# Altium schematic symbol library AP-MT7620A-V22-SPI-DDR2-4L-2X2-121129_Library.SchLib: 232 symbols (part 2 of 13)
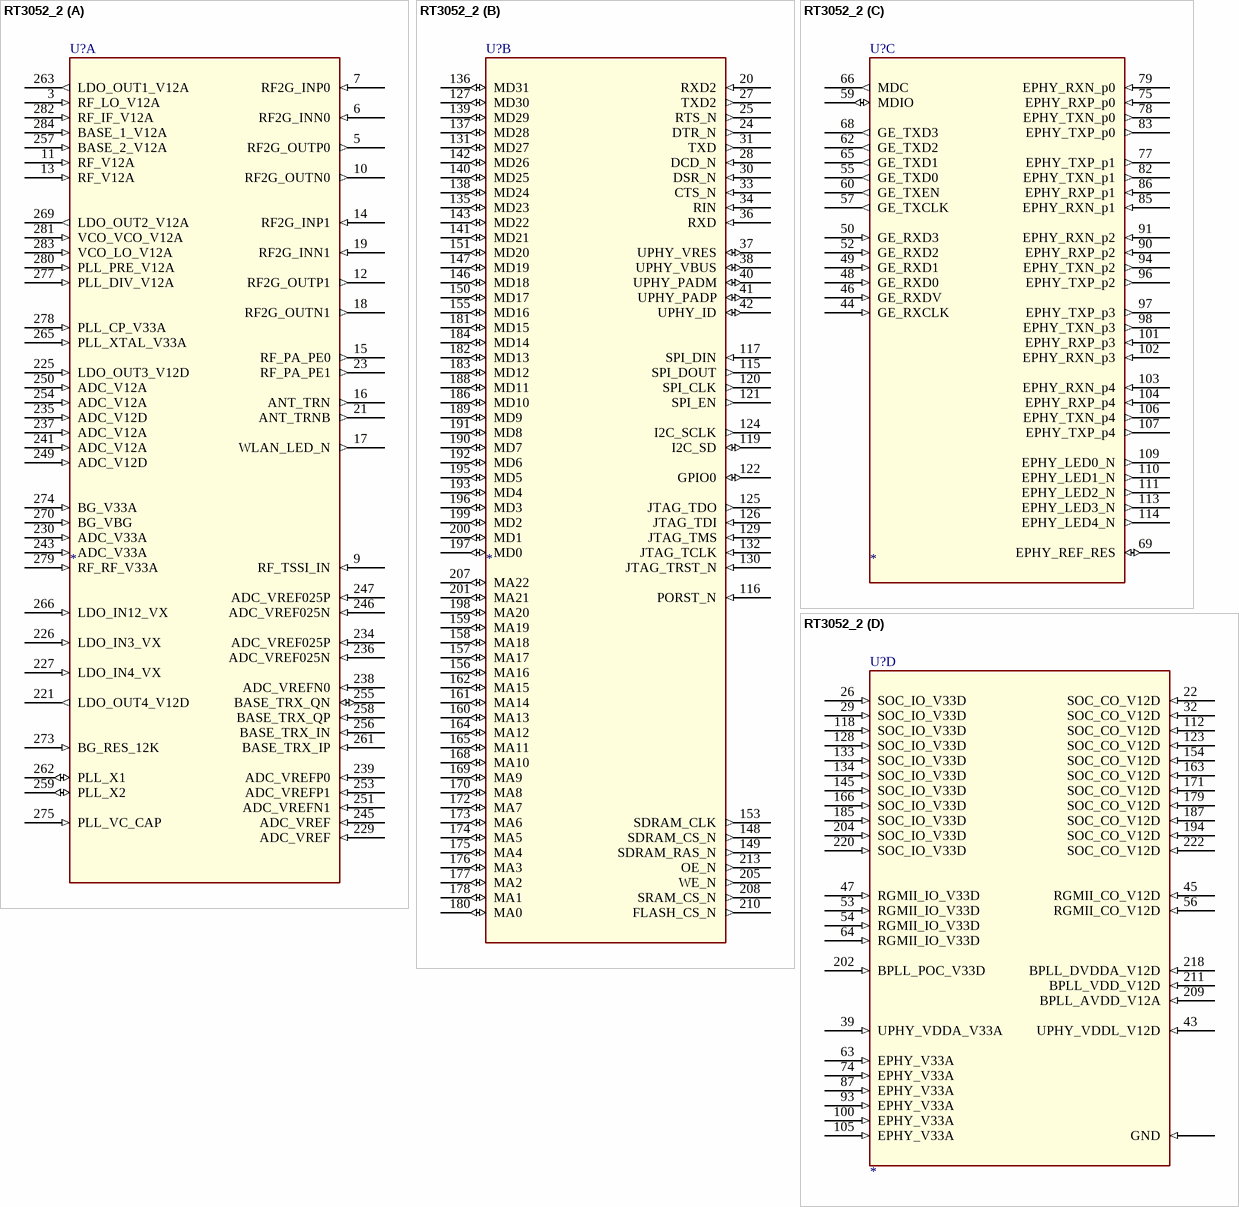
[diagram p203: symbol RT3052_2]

## RT3052_2
designator U?
footprint QFN285
part A pins: 3 RF_LO_V12A (in), 5 RF2G_OUTP0 (out), 6 RF2G_INN0 (in), 7 RF2G_INP0 (in), 9 RF_TSSI_IN (in), 10 RF2G_OUTN0 (out), 11 RF_V12A (in), 12 RF2G_OUTP1 (out), 13 RF_V12A (in), 14 RF2G_INP1 (in), 15 RF_PA_PE0 (out), 16 ANT_TRN (out), 17 WLAN_LED_N (out), 18 RF2G_OUTN1 (out), 19 RF2G_INN1 (in), 21 ANT_TRNB (out), 23 RF_PA_PE1 (out), 221 LDO_OUT4_V12D (out), 225 LDO_OUT3_V12D (in), 226 LDO_IN3_VX (in), 227 LDO_IN4_VX (in), 229 ADC_VREF (in), 230 ADC_V33A (in), 234 ADC_VREF025P (in), 235 ADC_V12D (in), 236 ADC_VREF025N (in), 237 ADC_V12A (in), 238 ADC_VREFN0 (in), 239 ADC_VREFP0 (in), 241 ADC_V12A (in), 243 ADC_V33A (in), 245 ADC_VREF (in), 246 ADC_VREF025N (in), 247 ADC_VREF025P (in), 249 ADC_V12D (in), 250 ADC_V12A (in), 251 ADC_VREFN1 (in), 253 ADC_VREFP1 (in), 254 ADC_V12A (in), 255 BASE_TRX_QN (io), 256 BASE_TRX_IN (in), 257 BASE_2_V12A (in), 258 BASE_TRX_QP (in), 259 PLL_X2 (io), 261 BASE_TRX_IP (in), 262 PLL_X1 (io), 263 LDO_OUT1_V12A (out), 265 PLL_XTAL_V33A (in), 266 LDO_IN12_VX (in), 269 LDO_OUT2_V12A (out), 270 BG_VBG (in), 273 BG_RES_12K (in), 274 BG_V33A (in), 275 PLL_VC_CAP (in), 277 PLL_DIV_V12A (in), 278 PLL_CP_V33A (in), 279 RF_RF_V33A (in), 280 PLL_PRE_V12A (in), 281 VCO_VCO_V12A (in), 282 RF_IF_V12A (in), 283 VCO_LO_V12A (in), 284 BASE_1_V12A (in)
part B pins: 20 RXD2 (in), 24 DTR_N (out), 25 RTS_N (out), 27 TXD2 (out), 28 DCD_N (in), 30 DSR_N (in), 31 TXD (out), 33 CTS_N (in), 34 RIN (in), 36 RXD (in), 37 UPHY_VRES (io), 38 UPHY_VBUS (io), 40 UPHY_PADM (io), 41 UPHY_PADP (io), 42 UPHY_ID (io), 115 SPI_DOUT (out), 116 PORST_N (in), 117 SPI_DIN (in), 119 I2C_SD (io), 120 SPI_CLK (out), 121 SPI_EN (out), 122 GPIO0 (io), 124 I2C_SCLK (out), 125 JTAG_TDO (out), 126 JTAG_TDI (in), 127 MD30 (io), 129 JTAG_TMS (in), 130 JTAG_TRST_N (in), 131 MD27 (io), 132 JTAG_TCLK (in), 135 MD23 (io), 136 MD31 (io), 137 MD28 (io), 138 MD24 (io), 139 MD29 (io), 140 MD25 (io), 141 MD21 (io), 142 MD26 (io), 143 MD22 (io), 146 MD18 (io), 147 MD19 (io), 148 SDRAM_CS_N (out), 149 SDRAM_RAS_N (out), 150 MD17 (io), 151 MD20 (io), 153 SDRAM_CLK (out), 155 MD16 (io), 156 MA16 (io), 157 MA17 (io), 158 MA18 (io), 159 MA19 (io), 160 MA13 (io), 161 MA14 (io), 162 MA15 (io), 164 MA12 (io), 165 MA11 (io), 168 MA10 (io), 169 MA9 (io), 170 MA8 (io), 172 MA7 (io), 173 MA6 (io), 174 MA5 (io), 175 MA4 (io), 176 MA3 (io), 177 MA2 (io), 178 MA1 (io), 180 MA0 (io), 181 MD15 (io), 182 MD13 (io), 183 MD12 (io), 184 MD14 (io), 186 MD10 (io), 188 MD11 (io), 189 MD9 (io), 190 MD7 (io), 191 MD8 (io), 192 MD6 (io), 193 MD4 (io), 195 MD5 (io), 196 MD3 (io), 197 MD0 (io), 198 MA20 (io), 199 MD2 (io), 200 MD1 (io), 201 MA21 (io), 205 WE_N (out), 207 MA22 (io), 208 SRAM_CS_N (out), 210 FLASH_CS_N (out), 213 OE_N (out)
part C pins: 44 GE_RXCLK (in), 46 GE_RXDV (in), 48 GE_RXD0 (in), 49 GE_RXD1 (in), 50 GE_RXD3 (in), 52 GE_RXD2 (in), 55 GE_TXD0 (out), 57 GE_TXCLK (out), 59 MDIO (io), 60 GE_TXEN (out), 62 GE_TXD2 (out), 65 GE_TXD1 (out), 66 MDC (out), 68 GE_TXD3 (out), 69 EPHY_REF_RES (io), 75 EPHY_RXP_p0 (in), 77 EPHY_TXP_p1 (out), 78 EPHY_TXN_p0 (out), 79 EPHY_RXN_p0 (in), 82 EPHY_TXN_p1 (out), 83 EPHY_TXP_p0 (out), 85 EPHY_RXN_p1 (in), 86 EPHY_RXP_p1 (in), 90 EPHY_RXP_p2 (in), 91 EPHY_RXN_p2 (in), 94 EPHY_TXN_p2 (out), 96 EPHY_TXP_p2 (out), 97 EPHY_TXP_p3 (out), 98 EPHY_TXN_p3 (out), 101 EPHY_RXP_p3 (in), 102 EPHY_RXN_p3 (in), 103 EPHY_RXN_p4 (in), 104 EPHY_RXP_p4 (in), 106 EPHY_TXN_p4 (out), 107 EPHY_TXP_p4 (out), 109 EPHY_LED0_N (out), 110 EPHY_LED1_N (out), 111 EPHY_LED2_N (out), 113 EPHY_LED3_N (out), 114 EPHY_LED4_N (out)
part D pins: 22 SOC_CO_V12D (in), 26 SOC_IO_V33D (in), 29 SOC_IO_V33D (in), 32 SOC_CO_V12D (in), 39 UPHY_VDDA_V33A (in), 43 UPHY_VDDL_V12D (in), 45 RGMII_CO_V12D (in), 47 RGMII_IO_V33D (in), 53 RGMII_IO_V33D (in), 54 RGMII_IO_V33D (in), 56 RGMII_CO_V12D (in), 63 EPHY_V33A (in), 64 RGMII_IO_V33D (in), 74 EPHY_V33A (in), 87 EPHY_V33A (in), 93 EPHY_V33A (in), 100 EPHY_V33A (in), 105 EPHY_V33A (in), 112 SOC_CO_V12D (in), 118 SOC_IO_V33D (in), 123 SOC_CO_V12D (in), 128 SOC_IO_V33D (in), 133 SOC_IO_V33D (in), 134 SOC_IO_V33D (in), 145 SOC_IO_V33D (in), 154 SOC_CO_V12D (in), 163 SOC_CO_V12D (in), 166 SOC_IO_V33D (in), 171 SOC_CO_V12D (in), 179 SOC_CO_V12D (in), 185 SOC_IO_V33D (in), 187 SOC_CO_V12D (in), 194 SOC_CO_V12D (in), 202 BPLL_POC_V33D (in), 204 SOC_IO_V33D (in), 209 BPLL_AVDD_V12A (in), 211 BPLL_VDD_V12D (in), 218 BPLL_DVDDA_V12D (in), 220 SOC_IO_V33D (in), 222 SOC_CO_V12D (in), GND (in)

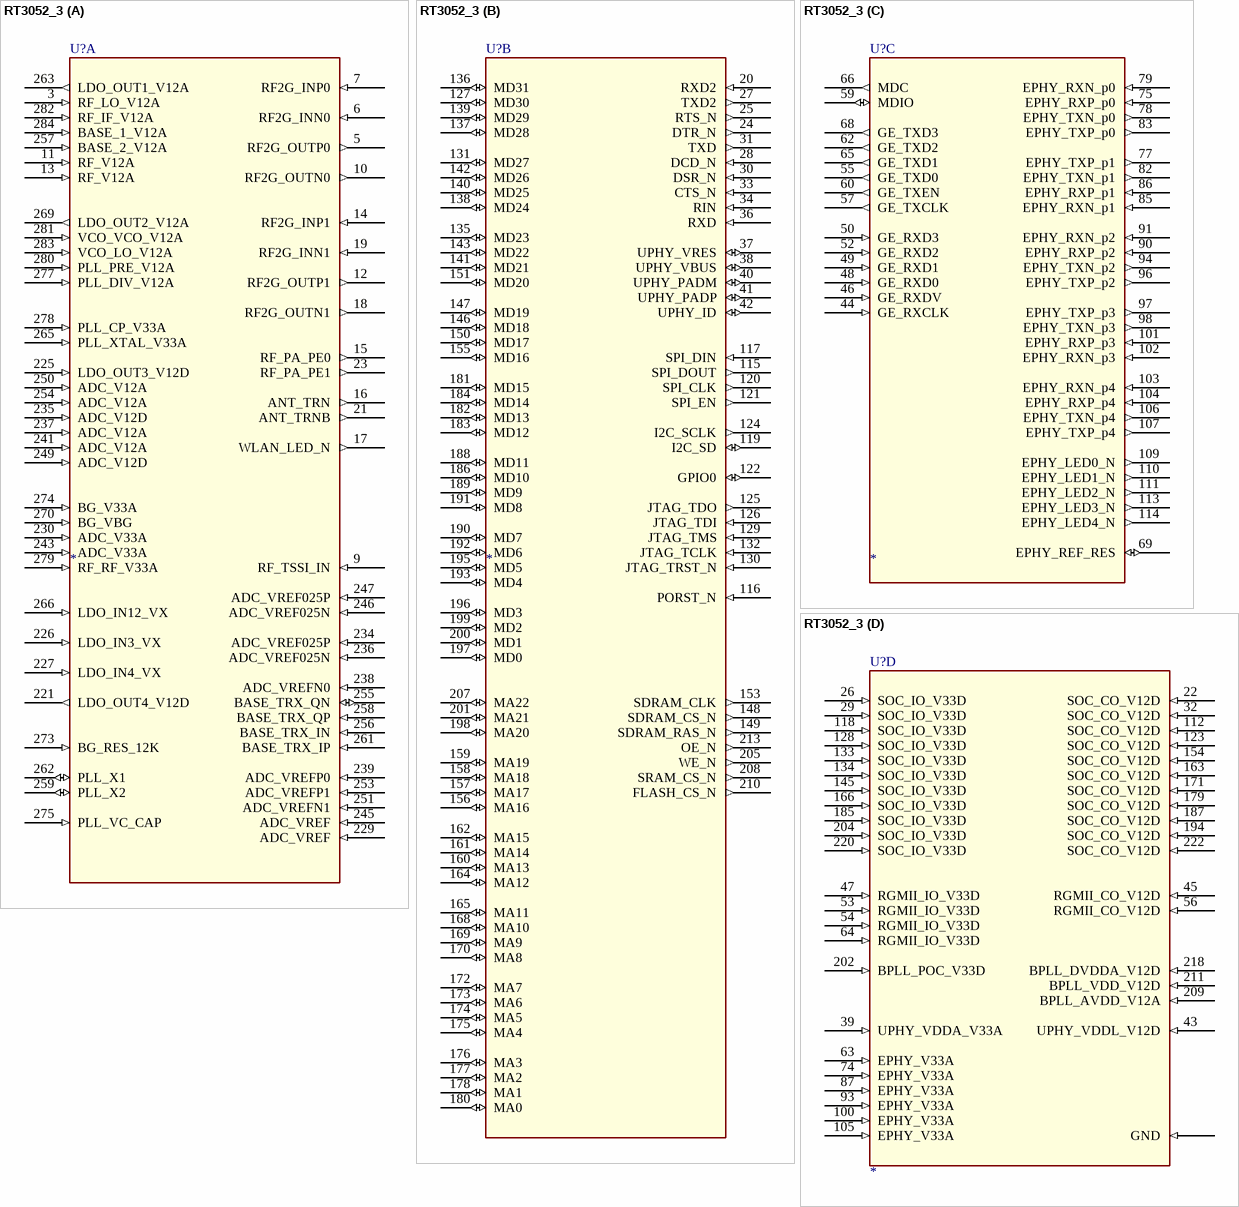
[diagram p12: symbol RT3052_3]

## RT3052_3
designator U?
footprint QFN285
part A pins: 3 RF_LO_V12A (in), 5 RF2G_OUTP0 (out), 6 RF2G_INN0 (in), 7 RF2G_INP0 (in), 9 RF_TSSI_IN (in), 10 RF2G_OUTN0 (out), 11 RF_V12A (in), 12 RF2G_OUTP1 (out), 13 RF_V12A (in), 14 RF2G_INP1 (in), 15 RF_PA_PE0 (out), 16 ANT_TRN (out), 17 WLAN_LED_N (out), 18 RF2G_OUTN1 (out), 19 RF2G_INN1 (in), 21 ANT_TRNB (out), 23 RF_PA_PE1 (out), 221 LDO_OUT4_V12D (out), 225 LDO_OUT3_V12D (in), 226 LDO_IN3_VX (in), 227 LDO_IN4_VX (in), 229 ADC_VREF (in), 230 ADC_V33A (in), 234 ADC_VREF025P (in), 235 ADC_V12D (in), 236 ADC_VREF025N (in), 237 ADC_V12A (in), 238 ADC_VREFN0 (in), 239 ADC_VREFP0 (in), 241 ADC_V12A (in), 243 ADC_V33A (in), 245 ADC_VREF (in), 246 ADC_VREF025N (in), 247 ADC_VREF025P (in), 249 ADC_V12D (in), 250 ADC_V12A (in), 251 ADC_VREFN1 (in), 253 ADC_VREFP1 (in), 254 ADC_V12A (in), 255 BASE_TRX_QN (io), 256 BASE_TRX_IN (in), 257 BASE_2_V12A (in), 258 BASE_TRX_QP (in), 259 PLL_X2 (io), 261 BASE_TRX_IP (in), 262 PLL_X1 (io), 263 LDO_OUT1_V12A (out), 265 PLL_XTAL_V33A (in), 266 LDO_IN12_VX (in), 269 LDO_OUT2_V12A (out), 270 BG_VBG (in), 273 BG_RES_12K (in), 274 BG_V33A (in), 275 PLL_VC_CAP (in), 277 PLL_DIV_V12A (in), 278 PLL_CP_V33A (in), 279 RF_RF_V33A (in), 280 PLL_PRE_V12A (in), 281 VCO_VCO_V12A (in), 282 RF_IF_V12A (in), 283 VCO_LO_V12A (in), 284 BASE_1_V12A (in)
part B pins: 20 RXD2 (in), 24 DTR_N (out), 25 RTS_N (out), 27 TXD2 (out), 28 DCD_N (in), 30 DSR_N (in), 31 TXD (out), 33 CTS_N (in), 34 RIN (in), 36 RXD (in), 37 UPHY_VRES (io), 38 UPHY_VBUS (io), 40 UPHY_PADM (io), 41 UPHY_PADP (io), 42 UPHY_ID (io), 115 SPI_DOUT (out), 116 PORST_N (in), 117 SPI_DIN (in), 119 I2C_SD (io), 120 SPI_CLK (out), 121 SPI_EN (out), 122 GPIO0 (io), 124 I2C_SCLK (out), 125 JTAG_TDO (out), 126 JTAG_TDI (in), 127 MD30 (io), 129 JTAG_TMS (in), 130 JTAG_TRST_N (in), 131 MD27 (io), 132 JTAG_TCLK (in), 135 MD23 (io), 136 MD31 (io), 137 MD28 (io), 138 MD24 (io), 139 MD29 (io), 140 MD25 (io), 141 MD21 (io), 142 MD26 (io), 143 MD22 (io), 146 MD18 (io), 147 MD19 (io), 148 SDRAM_CS_N (out), 149 SDRAM_RAS_N (out), 150 MD17 (io), 151 MD20 (io), 153 SDRAM_CLK (out), 155 MD16 (io), 156 MA16 (io), 157 MA17 (io), 158 MA18 (io), 159 MA19 (io), 160 MA13 (io), 161 MA14 (io), 162 MA15 (io), 164 MA12 (io), 165 MA11 (io), 168 MA10 (io), 169 MA9 (io), 170 MA8 (io), 172 MA7 (io), 173 MA6 (io), 174 MA5 (io), 175 MA4 (io), 176 MA3 (io), 177 MA2 (io), 178 MA1 (io), 180 MA0 (io), 181 MD15 (io), 182 MD13 (io), 183 MD12 (io), 184 MD14 (io), 186 MD10 (io), 188 MD11 (io), 189 MD9 (io), 190 MD7 (io), 191 MD8 (io), 192 MD6 (io), 193 MD4 (io), 195 MD5 (io), 196 MD3 (io), 197 MD0 (io), 198 MA20 (io), 199 MD2 (io), 200 MD1 (io), 201 MA21 (io), 205 WE_N (out), 207 MA22 (io), 208 SRAM_CS_N (out), 210 FLASH_CS_N (out), 213 OE_N (out)
part C pins: 44 GE_RXCLK (in), 46 GE_RXDV (in), 48 GE_RXD0 (in), 49 GE_RXD1 (in), 50 GE_RXD3 (in), 52 GE_RXD2 (in), 55 GE_TXD0 (out), 57 GE_TXCLK (out), 59 MDIO (io), 60 GE_TXEN (out), 62 GE_TXD2 (out), 65 GE_TXD1 (out), 66 MDC (out), 68 GE_TXD3 (out), 69 EPHY_REF_RES (io), 75 EPHY_RXP_p0 (in), 77 EPHY_TXP_p1 (out), 78 EPHY_TXN_p0 (out), 79 EPHY_RXN_p0 (in), 82 EPHY_TXN_p1 (out), 83 EPHY_TXP_p0 (out), 85 EPHY_RXN_p1 (in), 86 EPHY_RXP_p1 (in), 90 EPHY_RXP_p2 (in), 91 EPHY_RXN_p2 (in), 94 EPHY_TXN_p2 (out), 96 EPHY_TXP_p2 (out), 97 EPHY_TXP_p3 (out), 98 EPHY_TXN_p3 (out), 101 EPHY_RXP_p3 (in), 102 EPHY_RXN_p3 (in), 103 EPHY_RXN_p4 (in), 104 EPHY_RXP_p4 (in), 106 EPHY_TXN_p4 (out), 107 EPHY_TXP_p4 (out), 109 EPHY_LED0_N (out), 110 EPHY_LED1_N (out), 111 EPHY_LED2_N (out), 113 EPHY_LED3_N (out), 114 EPHY_LED4_N (out)
part D pins: 22 SOC_CO_V12D (in), 26 SOC_IO_V33D (in), 29 SOC_IO_V33D (in), 32 SOC_CO_V12D (in), 39 UPHY_VDDA_V33A (in), 43 UPHY_VDDL_V12D (in), 45 RGMII_CO_V12D (in), 47 RGMII_IO_V33D (in), 53 RGMII_IO_V33D (in), 54 RGMII_IO_V33D (in), 56 RGMII_CO_V12D (in), 63 EPHY_V33A (in), 64 RGMII_IO_V33D (in), 74 EPHY_V33A (in), 87 EPHY_V33A (in), 93 EPHY_V33A (in), 100 EPHY_V33A (in), 105 EPHY_V33A (in), 112 SOC_CO_V12D (in), 118 SOC_IO_V33D (in), 123 SOC_CO_V12D (in), 128 SOC_IO_V33D (in), 133 SOC_IO_V33D (in), 134 SOC_IO_V33D (in), 145 SOC_IO_V33D (in), 154 SOC_CO_V12D (in), 163 SOC_CO_V12D (in), 166 SOC_IO_V33D (in), 171 SOC_CO_V12D (in), 179 SOC_CO_V12D (in), 185 SOC_IO_V33D (in), 187 SOC_CO_V12D (in), 194 SOC_CO_V12D (in), 202 BPLL_POC_V33D (in), 204 SOC_IO_V33D (in), 209 BPLL_AVDD_V12A (in), 211 BPLL_VDD_V12D (in), 218 BPLL_DVDDA_V12D (in), 220 SOC_IO_V33D (in), 222 SOC_CO_V12D (in), GND (in)

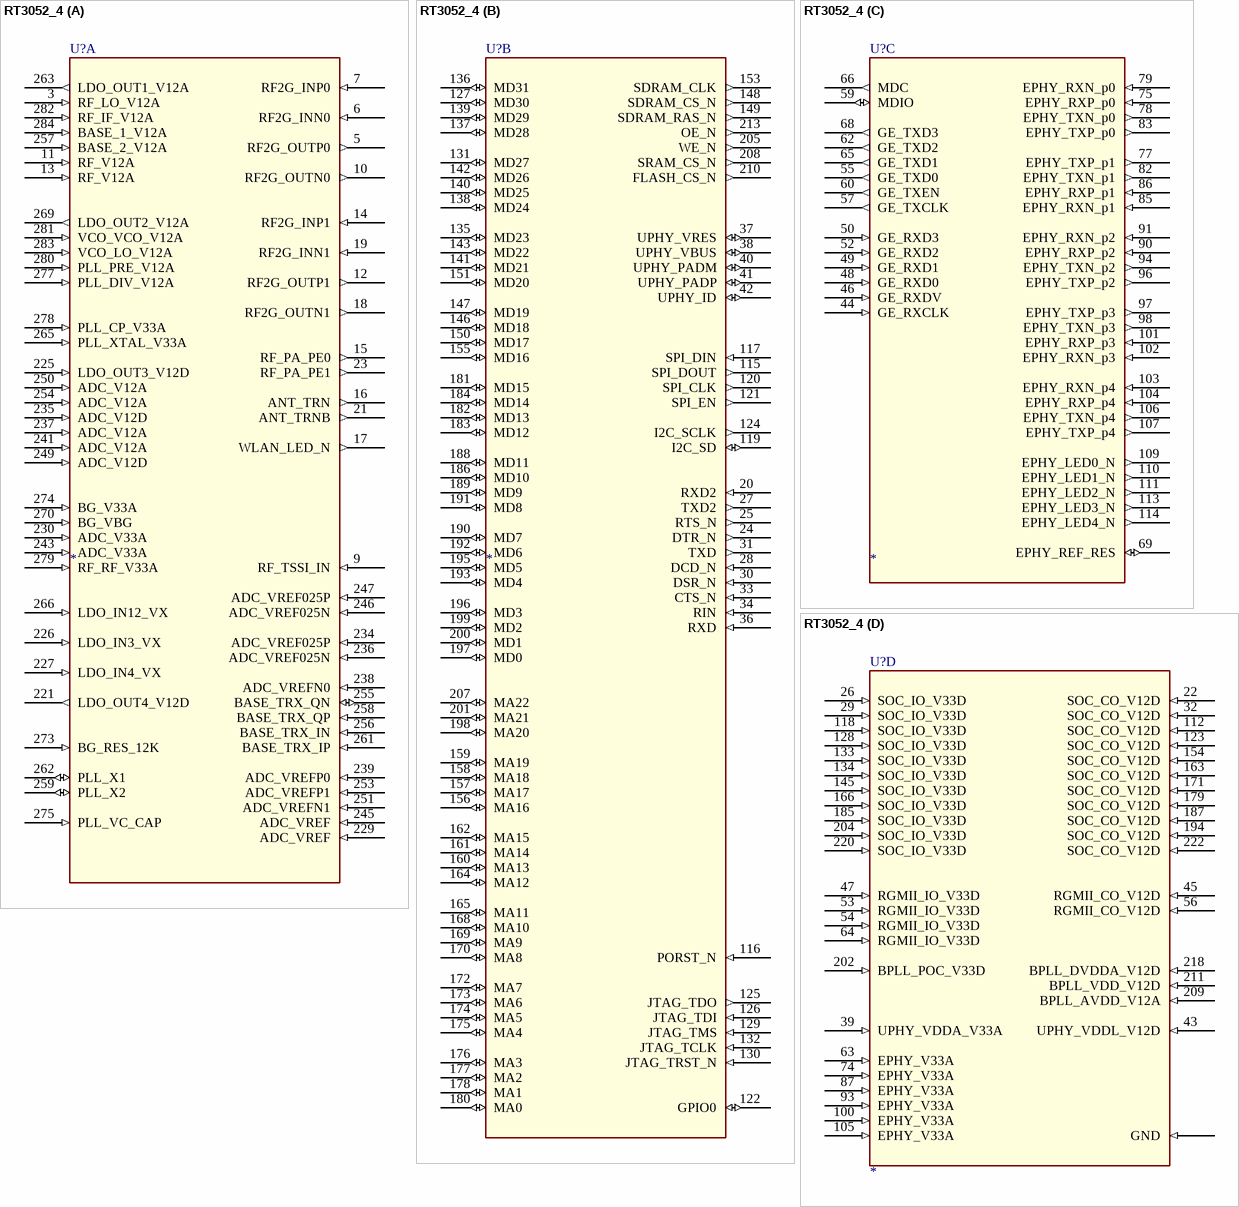
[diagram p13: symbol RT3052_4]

## RT3052_4
designator U?
footprint QFN285
part A pins: 3 RF_LO_V12A (in), 5 RF2G_OUTP0 (out), 6 RF2G_INN0 (in), 7 RF2G_INP0 (in), 9 RF_TSSI_IN (in), 10 RF2G_OUTN0 (out), 11 RF_V12A (in), 12 RF2G_OUTP1 (out), 13 RF_V12A (in), 14 RF2G_INP1 (in), 15 RF_PA_PE0 (out), 16 ANT_TRN (out), 17 WLAN_LED_N (out), 18 RF2G_OUTN1 (out), 19 RF2G_INN1 (in), 21 ANT_TRNB (out), 23 RF_PA_PE1 (out), 221 LDO_OUT4_V12D (out), 225 LDO_OUT3_V12D (in), 226 LDO_IN3_VX (in), 227 LDO_IN4_VX (in), 229 ADC_VREF (in), 230 ADC_V33A (in), 234 ADC_VREF025P (in), 235 ADC_V12D (in), 236 ADC_VREF025N (in), 237 ADC_V12A (in), 238 ADC_VREFN0 (in), 239 ADC_VREFP0 (in), 241 ADC_V12A (in), 243 ADC_V33A (in), 245 ADC_VREF (in), 246 ADC_VREF025N (in), 247 ADC_VREF025P (in), 249 ADC_V12D (in), 250 ADC_V12A (in), 251 ADC_VREFN1 (in), 253 ADC_VREFP1 (in), 254 ADC_V12A (in), 255 BASE_TRX_QN (io), 256 BASE_TRX_IN (in), 257 BASE_2_V12A (in), 258 BASE_TRX_QP (in), 259 PLL_X2 (io), 261 BASE_TRX_IP (in), 262 PLL_X1 (io), 263 LDO_OUT1_V12A (out), 265 PLL_XTAL_V33A (in), 266 LDO_IN12_VX (in), 269 LDO_OUT2_V12A (out), 270 BG_VBG (in), 273 BG_RES_12K (in), 274 BG_V33A (in), 275 PLL_VC_CAP (in), 277 PLL_DIV_V12A (in), 278 PLL_CP_V33A (in), 279 RF_RF_V33A (in), 280 PLL_PRE_V12A (in), 281 VCO_VCO_V12A (in), 282 RF_IF_V12A (in), 283 VCO_LO_V12A (in), 284 BASE_1_V12A (in)
part B pins: 20 RXD2 (in), 24 DTR_N (out), 25 RTS_N (out), 27 TXD2 (out), 28 DCD_N (in), 30 DSR_N (in), 31 TXD (out), 33 CTS_N (in), 34 RIN (in), 36 RXD (in), 37 UPHY_VRES (io), 38 UPHY_VBUS (io), 40 UPHY_PADM (io), 41 UPHY_PADP (io), 42 UPHY_ID (io), 115 SPI_DOUT (out), 116 PORST_N (in), 117 SPI_DIN (in), 119 I2C_SD (io), 120 SPI_CLK (out), 121 SPI_EN (out), 122 GPIO0 (io), 124 I2C_SCLK (out), 125 JTAG_TDO (out), 126 JTAG_TDI (in), 127 MD30 (io), 129 JTAG_TMS (in), 130 JTAG_TRST_N (in), 131 MD27 (io), 132 JTAG_TCLK (in), 135 MD23 (io), 136 MD31 (io), 137 MD28 (io), 138 MD24 (io), 139 MD29 (io), 140 MD25 (io), 141 MD21 (io), 142 MD26 (io), 143 MD22 (io), 146 MD18 (io), 147 MD19 (io), 148 SDRAM_CS_N (out), 149 SDRAM_RAS_N (out), 150 MD17 (io), 151 MD20 (io), 153 SDRAM_CLK (out), 155 MD16 (io), 156 MA16 (io), 157 MA17 (io), 158 MA18 (io), 159 MA19 (io), 160 MA13 (io), 161 MA14 (io), 162 MA15 (io), 164 MA12 (io), 165 MA11 (io), 168 MA10 (io), 169 MA9 (io), 170 MA8 (io), 172 MA7 (io), 173 MA6 (io), 174 MA5 (io), 175 MA4 (io), 176 MA3 (io), 177 MA2 (io), 178 MA1 (io), 180 MA0 (io), 181 MD15 (io), 182 MD13 (io), 183 MD12 (io), 184 MD14 (io), 186 MD10 (io), 188 MD11 (io), 189 MD9 (io), 190 MD7 (io), 191 MD8 (io), 192 MD6 (io), 193 MD4 (io), 195 MD5 (io), 196 MD3 (io), 197 MD0 (io), 198 MA20 (io), 199 MD2 (io), 200 MD1 (io), 201 MA21 (io), 205 WE_N (out), 207 MA22 (io), 208 SRAM_CS_N (out), 210 FLASH_CS_N (out), 213 OE_N (out)
part C pins: 44 GE_RXCLK (in), 46 GE_RXDV (in), 48 GE_RXD0 (in), 49 GE_RXD1 (in), 50 GE_RXD3 (in), 52 GE_RXD2 (in), 55 GE_TXD0 (out), 57 GE_TXCLK (out), 59 MDIO (io), 60 GE_TXEN (out), 62 GE_TXD2 (out), 65 GE_TXD1 (out), 66 MDC (out), 68 GE_TXD3 (out), 69 EPHY_REF_RES (io), 75 EPHY_RXP_p0 (in), 77 EPHY_TXP_p1 (out), 78 EPHY_TXN_p0 (out), 79 EPHY_RXN_p0 (in), 82 EPHY_TXN_p1 (out), 83 EPHY_TXP_p0 (out), 85 EPHY_RXN_p1 (in), 86 EPHY_RXP_p1 (in), 90 EPHY_RXP_p2 (in), 91 EPHY_RXN_p2 (in), 94 EPHY_TXN_p2 (out), 96 EPHY_TXP_p2 (out), 97 EPHY_TXP_p3 (out), 98 EPHY_TXN_p3 (out), 101 EPHY_RXP_p3 (in), 102 EPHY_RXN_p3 (in), 103 EPHY_RXN_p4 (in), 104 EPHY_RXP_p4 (in), 106 EPHY_TXN_p4 (out), 107 EPHY_TXP_p4 (out), 109 EPHY_LED0_N (out), 110 EPHY_LED1_N (out), 111 EPHY_LED2_N (out), 113 EPHY_LED3_N (out), 114 EPHY_LED4_N (out)
part D pins: 22 SOC_CO_V12D (in), 26 SOC_IO_V33D (in), 29 SOC_IO_V33D (in), 32 SOC_CO_V12D (in), 39 UPHY_VDDA_V33A (in), 43 UPHY_VDDL_V12D (in), 45 RGMII_CO_V12D (in), 47 RGMII_IO_V33D (in), 53 RGMII_IO_V33D (in), 54 RGMII_IO_V33D (in), 56 RGMII_CO_V12D (in), 63 EPHY_V33A (in), 64 RGMII_IO_V33D (in), 74 EPHY_V33A (in), 87 EPHY_V33A (in), 93 EPHY_V33A (in), 100 EPHY_V33A (in), 105 EPHY_V33A (in), 112 SOC_CO_V12D (in), 118 SOC_IO_V33D (in), 123 SOC_CO_V12D (in), 128 SOC_IO_V33D (in), 133 SOC_IO_V33D (in), 134 SOC_IO_V33D (in), 145 SOC_IO_V33D (in), 154 SOC_CO_V12D (in), 163 SOC_CO_V12D (in), 166 SOC_IO_V33D (in), 171 SOC_CO_V12D (in), 179 SOC_CO_V12D (in), 185 SOC_IO_V33D (in), 187 SOC_CO_V12D (in), 194 SOC_CO_V12D (in), 202 BPLL_POC_V33D (in), 204 SOC_IO_V33D (in), 209 BPLL_AVDD_V12A (in), 211 BPLL_VDD_V12D (in), 218 BPLL_DVDDA_V12D (in), 220 SOC_IO_V33D (in), 222 SOC_CO_V12D (in), GND (in)

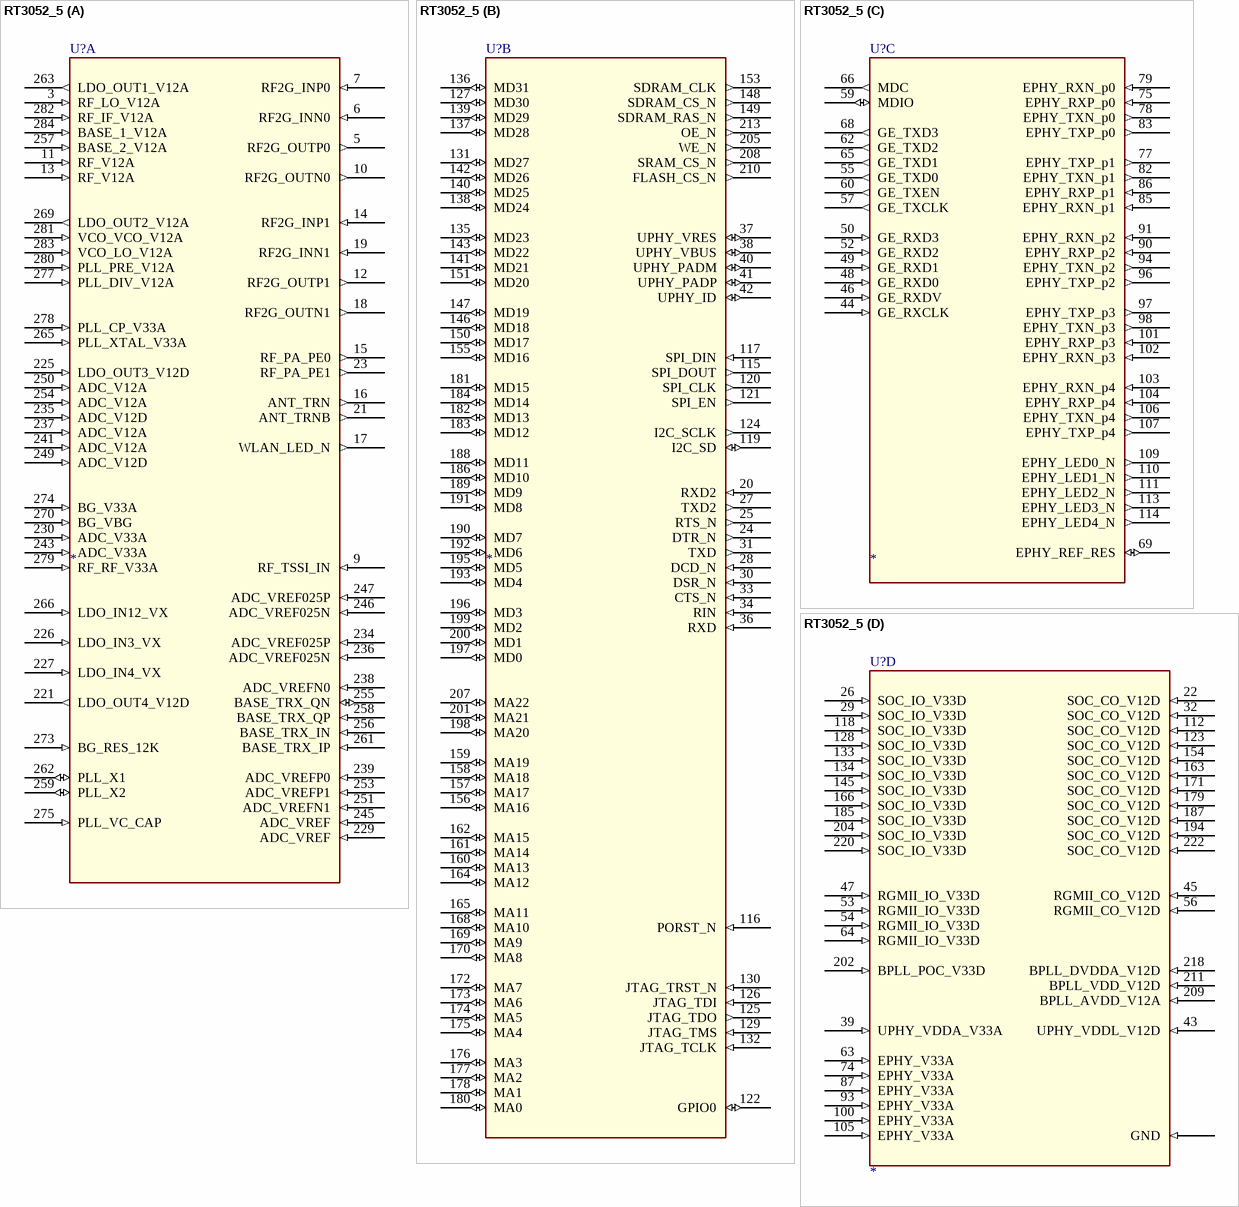
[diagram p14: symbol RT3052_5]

## RT3052_5
designator U?
footprint QFN285
part A pins: 3 RF_LO_V12A (in), 5 RF2G_OUTP0 (out), 6 RF2G_INN0 (in), 7 RF2G_INP0 (in), 9 RF_TSSI_IN (in), 10 RF2G_OUTN0 (out), 11 RF_V12A (in), 12 RF2G_OUTP1 (out), 13 RF_V12A (in), 14 RF2G_INP1 (in), 15 RF_PA_PE0 (out), 16 ANT_TRN (out), 17 WLAN_LED_N (out), 18 RF2G_OUTN1 (out), 19 RF2G_INN1 (in), 21 ANT_TRNB (out), 23 RF_PA_PE1 (out), 221 LDO_OUT4_V12D (out), 225 LDO_OUT3_V12D (in), 226 LDO_IN3_VX (in), 227 LDO_IN4_VX (in), 229 ADC_VREF (in), 230 ADC_V33A (in), 234 ADC_VREF025P (in), 235 ADC_V12D (in), 236 ADC_VREF025N (in), 237 ADC_V12A (in), 238 ADC_VREFN0 (in), 239 ADC_VREFP0 (in), 241 ADC_V12A (in), 243 ADC_V33A (in), 245 ADC_VREF (in), 246 ADC_VREF025N (in), 247 ADC_VREF025P (in), 249 ADC_V12D (in), 250 ADC_V12A (in), 251 ADC_VREFN1 (in), 253 ADC_VREFP1 (in), 254 ADC_V12A (in), 255 BASE_TRX_QN (io), 256 BASE_TRX_IN (in), 257 BASE_2_V12A (in), 258 BASE_TRX_QP (in), 259 PLL_X2 (io), 261 BASE_TRX_IP (in), 262 PLL_X1 (io), 263 LDO_OUT1_V12A (out), 265 PLL_XTAL_V33A (in), 266 LDO_IN12_VX (in), 269 LDO_OUT2_V12A (out), 270 BG_VBG (in), 273 BG_RES_12K (in), 274 BG_V33A (in), 275 PLL_VC_CAP (in), 277 PLL_DIV_V12A (in), 278 PLL_CP_V33A (in), 279 RF_RF_V33A (in), 280 PLL_PRE_V12A (in), 281 VCO_VCO_V12A (in), 282 RF_IF_V12A (in), 283 VCO_LO_V12A (in), 284 BASE_1_V12A (in)
part B pins: 20 RXD2 (in), 24 DTR_N (out), 25 RTS_N (out), 27 TXD2 (out), 28 DCD_N (in), 30 DSR_N (in), 31 TXD (out), 33 CTS_N (in), 34 RIN (in), 36 RXD (in), 37 UPHY_VRES (io), 38 UPHY_VBUS (io), 40 UPHY_PADM (io), 41 UPHY_PADP (io), 42 UPHY_ID (io), 115 SPI_DOUT (out), 116 PORST_N (in), 117 SPI_DIN (in), 119 I2C_SD (io), 120 SPI_CLK (out), 121 SPI_EN (out), 122 GPIO0 (io), 124 I2C_SCLK (out), 125 JTAG_TDO (out), 126 JTAG_TDI (in), 127 MD30 (io), 129 JTAG_TMS (in), 130 JTAG_TRST_N (in), 131 MD27 (io), 132 JTAG_TCLK (in), 135 MD23 (io), 136 MD31 (io), 137 MD28 (io), 138 MD24 (io), 139 MD29 (io), 140 MD25 (io), 141 MD21 (io), 142 MD26 (io), 143 MD22 (io), 146 MD18 (io), 147 MD19 (io), 148 SDRAM_CS_N (out), 149 SDRAM_RAS_N (out), 150 MD17 (io), 151 MD20 (io), 153 SDRAM_CLK (out), 155 MD16 (io), 156 MA16 (io), 157 MA17 (io), 158 MA18 (io), 159 MA19 (io), 160 MA13 (io), 161 MA14 (io), 162 MA15 (io), 164 MA12 (io), 165 MA11 (io), 168 MA10 (io), 169 MA9 (io), 170 MA8 (io), 172 MA7 (io), 173 MA6 (io), 174 MA5 (io), 175 MA4 (io), 176 MA3 (io), 177 MA2 (io), 178 MA1 (io), 180 MA0 (io), 181 MD15 (io), 182 MD13 (io), 183 MD12 (io), 184 MD14 (io), 186 MD10 (io), 188 MD11 (io), 189 MD9 (io), 190 MD7 (io), 191 MD8 (io), 192 MD6 (io), 193 MD4 (io), 195 MD5 (io), 196 MD3 (io), 197 MD0 (io), 198 MA20 (io), 199 MD2 (io), 200 MD1 (io), 201 MA21 (io), 205 WE_N (out), 207 MA22 (io), 208 SRAM_CS_N (out), 210 FLASH_CS_N (out), 213 OE_N (out)
part C pins: 44 GE_RXCLK (in), 46 GE_RXDV (in), 48 GE_RXD0 (in), 49 GE_RXD1 (in), 50 GE_RXD3 (in), 52 GE_RXD2 (in), 55 GE_TXD0 (out), 57 GE_TXCLK (out), 59 MDIO (io), 60 GE_TXEN (out), 62 GE_TXD2 (out), 65 GE_TXD1 (out), 66 MDC (out), 68 GE_TXD3 (out), 69 EPHY_REF_RES (io), 75 EPHY_RXP_p0 (in), 77 EPHY_TXP_p1 (out), 78 EPHY_TXN_p0 (out), 79 EPHY_RXN_p0 (in), 82 EPHY_TXN_p1 (out), 83 EPHY_TXP_p0 (out), 85 EPHY_RXN_p1 (in), 86 EPHY_RXP_p1 (in), 90 EPHY_RXP_p2 (in), 91 EPHY_RXN_p2 (in), 94 EPHY_TXN_p2 (out), 96 EPHY_TXP_p2 (out), 97 EPHY_TXP_p3 (out), 98 EPHY_TXN_p3 (out), 101 EPHY_RXP_p3 (in), 102 EPHY_RXN_p3 (in), 103 EPHY_RXN_p4 (in), 104 EPHY_RXP_p4 (in), 106 EPHY_TXN_p4 (out), 107 EPHY_TXP_p4 (out), 109 EPHY_LED0_N (out), 110 EPHY_LED1_N (out), 111 EPHY_LED2_N (out), 113 EPHY_LED3_N (out), 114 EPHY_LED4_N (out)
part D pins: 22 SOC_CO_V12D (in), 26 SOC_IO_V33D (in), 29 SOC_IO_V33D (in), 32 SOC_CO_V12D (in), 39 UPHY_VDDA_V33A (in), 43 UPHY_VDDL_V12D (in), 45 RGMII_CO_V12D (in), 47 RGMII_IO_V33D (in), 53 RGMII_IO_V33D (in), 54 RGMII_IO_V33D (in), 56 RGMII_CO_V12D (in), 63 EPHY_V33A (in), 64 RGMII_IO_V33D (in), 74 EPHY_V33A (in), 87 EPHY_V33A (in), 93 EPHY_V33A (in), 100 EPHY_V33A (in), 105 EPHY_V33A (in), 112 SOC_CO_V12D (in), 118 SOC_IO_V33D (in), 123 SOC_CO_V12D (in), 128 SOC_IO_V33D (in), 133 SOC_IO_V33D (in), 134 SOC_IO_V33D (in), 145 SOC_IO_V33D (in), 154 SOC_CO_V12D (in), 163 SOC_CO_V12D (in), 166 SOC_IO_V33D (in), 171 SOC_CO_V12D (in), 179 SOC_CO_V12D (in), 185 SOC_IO_V33D (in), 187 SOC_CO_V12D (in), 194 SOC_CO_V12D (in), 202 BPLL_POC_V33D (in), 204 SOC_IO_V33D (in), 209 BPLL_AVDD_V12A (in), 211 BPLL_VDD_V12D (in), 218 BPLL_DVDDA_V12D (in), 220 SOC_IO_V33D (in), 222 SOC_CO_V12D (in), GND (in)

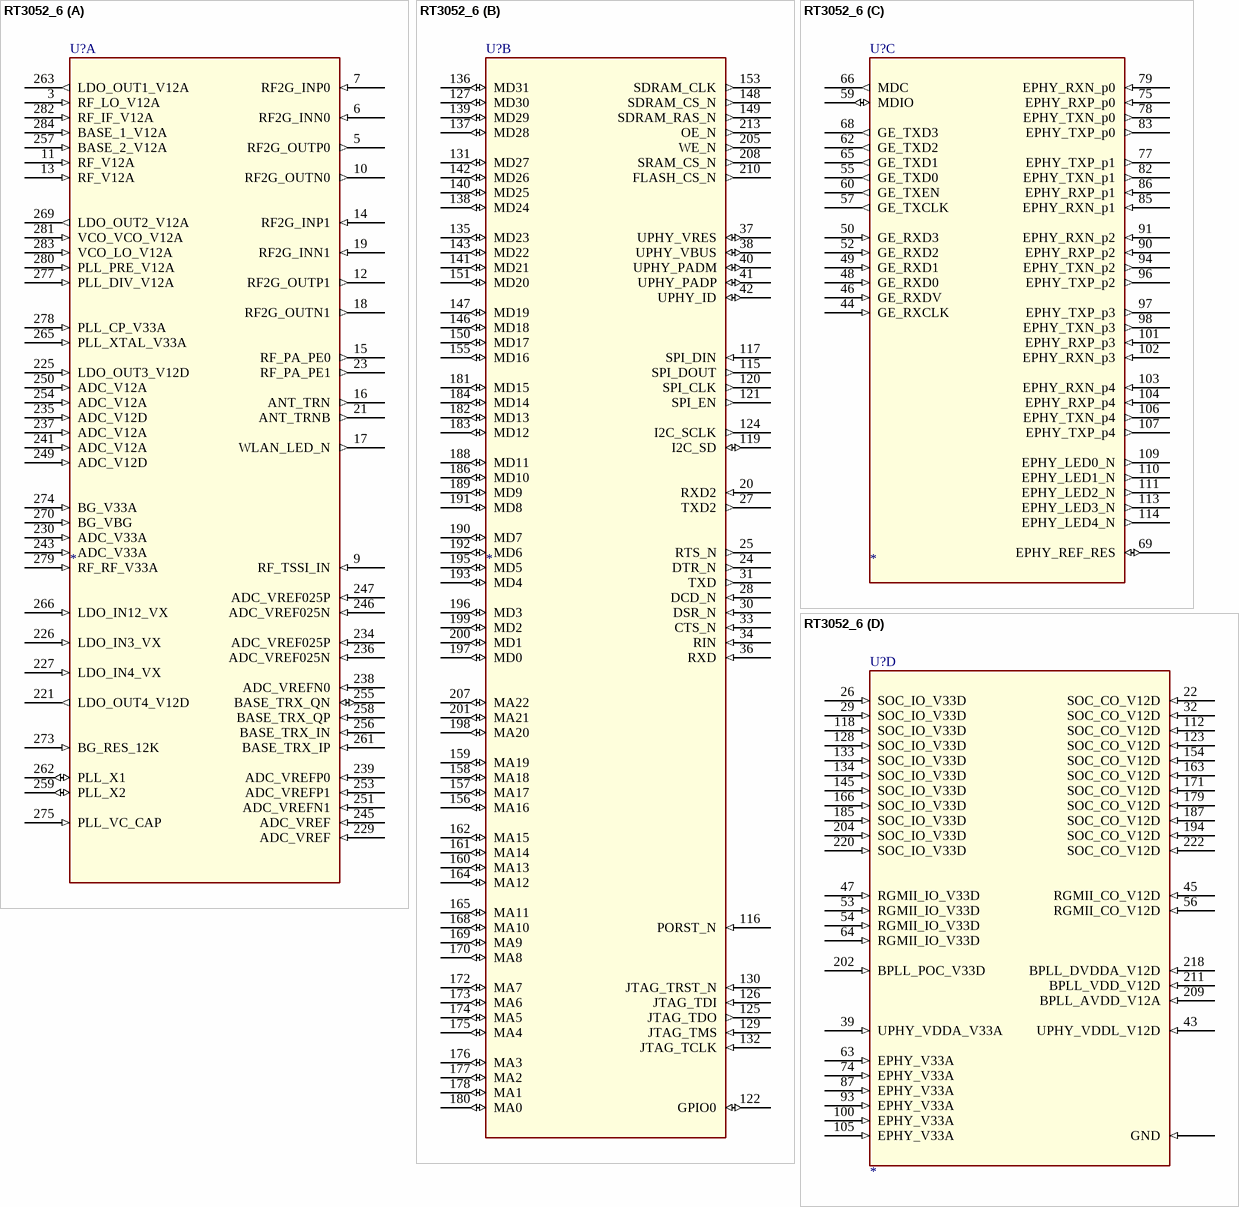
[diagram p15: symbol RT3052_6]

## RT3052_6
designator U?
footprint QFN285
part A pins: 3 RF_LO_V12A (in), 5 RF2G_OUTP0 (out), 6 RF2G_INN0 (in), 7 RF2G_INP0 (in), 9 RF_TSSI_IN (in), 10 RF2G_OUTN0 (out), 11 RF_V12A (in), 12 RF2G_OUTP1 (out), 13 RF_V12A (in), 14 RF2G_INP1 (in), 15 RF_PA_PE0 (out), 16 ANT_TRN (out), 17 WLAN_LED_N (out), 18 RF2G_OUTN1 (out), 19 RF2G_INN1 (in), 21 ANT_TRNB (out), 23 RF_PA_PE1 (out), 221 LDO_OUT4_V12D (out), 225 LDO_OUT3_V12D (in), 226 LDO_IN3_VX (in), 227 LDO_IN4_VX (in), 229 ADC_VREF (in), 230 ADC_V33A (in), 234 ADC_VREF025P (in), 235 ADC_V12D (in), 236 ADC_VREF025N (in), 237 ADC_V12A (in), 238 ADC_VREFN0 (in), 239 ADC_VREFP0 (in), 241 ADC_V12A (in), 243 ADC_V33A (in), 245 ADC_VREF (in), 246 ADC_VREF025N (in), 247 ADC_VREF025P (in), 249 ADC_V12D (in), 250 ADC_V12A (in), 251 ADC_VREFN1 (in), 253 ADC_VREFP1 (in), 254 ADC_V12A (in), 255 BASE_TRX_QN (io), 256 BASE_TRX_IN (in), 257 BASE_2_V12A (in), 258 BASE_TRX_QP (in), 259 PLL_X2 (io), 261 BASE_TRX_IP (in), 262 PLL_X1 (io), 263 LDO_OUT1_V12A (out), 265 PLL_XTAL_V33A (in), 266 LDO_IN12_VX (in), 269 LDO_OUT2_V12A (out), 270 BG_VBG (in), 273 BG_RES_12K (in), 274 BG_V33A (in), 275 PLL_VC_CAP (in), 277 PLL_DIV_V12A (in), 278 PLL_CP_V33A (in), 279 RF_RF_V33A (in), 280 PLL_PRE_V12A (in), 281 VCO_VCO_V12A (in), 282 RF_IF_V12A (in), 283 VCO_LO_V12A (in), 284 BASE_1_V12A (in)
part B pins: 20 RXD2 (in), 24 DTR_N (out), 25 RTS_N (out), 27 TXD2 (out), 28 DCD_N (in), 30 DSR_N (in), 31 TXD (out), 33 CTS_N (in), 34 RIN (in), 36 RXD (in), 37 UPHY_VRES (io), 38 UPHY_VBUS (io), 40 UPHY_PADM (io), 41 UPHY_PADP (io), 42 UPHY_ID (io), 115 SPI_DOUT (out), 116 PORST_N (in), 117 SPI_DIN (in), 119 I2C_SD (io), 120 SPI_CLK (out), 121 SPI_EN (out), 122 GPIO0 (io), 124 I2C_SCLK (out), 125 JTAG_TDO (out), 126 JTAG_TDI (in), 127 MD30 (io), 129 JTAG_TMS (in), 130 JTAG_TRST_N (in), 131 MD27 (io), 132 JTAG_TCLK (in), 135 MD23 (io), 136 MD31 (io), 137 MD28 (io), 138 MD24 (io), 139 MD29 (io), 140 MD25 (io), 141 MD21 (io), 142 MD26 (io), 143 MD22 (io), 146 MD18 (io), 147 MD19 (io), 148 SDRAM_CS_N (out), 149 SDRAM_RAS_N (out), 150 MD17 (io), 151 MD20 (io), 153 SDRAM_CLK (out), 155 MD16 (io), 156 MA16 (io), 157 MA17 (io), 158 MA18 (io), 159 MA19 (io), 160 MA13 (io), 161 MA14 (io), 162 MA15 (io), 164 MA12 (io), 165 MA11 (io), 168 MA10 (io), 169 MA9 (io), 170 MA8 (io), 172 MA7 (io), 173 MA6 (io), 174 MA5 (io), 175 MA4 (io), 176 MA3 (io), 177 MA2 (io), 178 MA1 (io), 180 MA0 (io), 181 MD15 (io), 182 MD13 (io), 183 MD12 (io), 184 MD14 (io), 186 MD10 (io), 188 MD11 (io), 189 MD9 (io), 190 MD7 (io), 191 MD8 (io), 192 MD6 (io), 193 MD4 (io), 195 MD5 (io), 196 MD3 (io), 197 MD0 (io), 198 MA20 (io), 199 MD2 (io), 200 MD1 (io), 201 MA21 (io), 205 WE_N (out), 207 MA22 (io), 208 SRAM_CS_N (out), 210 FLASH_CS_N (out), 213 OE_N (out)
part C pins: 44 GE_RXCLK (in), 46 GE_RXDV (in), 48 GE_RXD0 (in), 49 GE_RXD1 (in), 50 GE_RXD3 (in), 52 GE_RXD2 (in), 55 GE_TXD0 (out), 57 GE_TXCLK (out), 59 MDIO (io), 60 GE_TXEN (out), 62 GE_TXD2 (out), 65 GE_TXD1 (out), 66 MDC (out), 68 GE_TXD3 (out), 69 EPHY_REF_RES (io), 75 EPHY_RXP_p0 (in), 77 EPHY_TXP_p1 (out), 78 EPHY_TXN_p0 (out), 79 EPHY_RXN_p0 (in), 82 EPHY_TXN_p1 (out), 83 EPHY_TXP_p0 (out), 85 EPHY_RXN_p1 (in), 86 EPHY_RXP_p1 (in), 90 EPHY_RXP_p2 (in), 91 EPHY_RXN_p2 (in), 94 EPHY_TXN_p2 (out), 96 EPHY_TXP_p2 (out), 97 EPHY_TXP_p3 (out), 98 EPHY_TXN_p3 (out), 101 EPHY_RXP_p3 (in), 102 EPHY_RXN_p3 (in), 103 EPHY_RXN_p4 (in), 104 EPHY_RXP_p4 (in), 106 EPHY_TXN_p4 (out), 107 EPHY_TXP_p4 (out), 109 EPHY_LED0_N (out), 110 EPHY_LED1_N (out), 111 EPHY_LED2_N (out), 113 EPHY_LED3_N (out), 114 EPHY_LED4_N (out)
part D pins: 22 SOC_CO_V12D (in), 26 SOC_IO_V33D (in), 29 SOC_IO_V33D (in), 32 SOC_CO_V12D (in), 39 UPHY_VDDA_V33A (in), 43 UPHY_VDDL_V12D (in), 45 RGMII_CO_V12D (in), 47 RGMII_IO_V33D (in), 53 RGMII_IO_V33D (in), 54 RGMII_IO_V33D (in), 56 RGMII_CO_V12D (in), 63 EPHY_V33A (in), 64 RGMII_IO_V33D (in), 74 EPHY_V33A (in), 87 EPHY_V33A (in), 93 EPHY_V33A (in), 100 EPHY_V33A (in), 105 EPHY_V33A (in), 112 SOC_CO_V12D (in), 118 SOC_IO_V33D (in), 123 SOC_CO_V12D (in), 128 SOC_IO_V33D (in), 133 SOC_IO_V33D (in), 134 SOC_IO_V33D (in), 145 SOC_IO_V33D (in), 154 SOC_CO_V12D (in), 163 SOC_CO_V12D (in), 166 SOC_IO_V33D (in), 171 SOC_CO_V12D (in), 179 SOC_CO_V12D (in), 185 SOC_IO_V33D (in), 187 SOC_CO_V12D (in), 194 SOC_CO_V12D (in), 202 BPLL_POC_V33D (in), 204 SOC_IO_V33D (in), 209 BPLL_AVDD_V12A (in), 211 BPLL_VDD_V12D (in), 218 BPLL_DVDDA_V12D (in), 220 SOC_IO_V33D (in), 222 SOC_CO_V12D (in), GND (in)

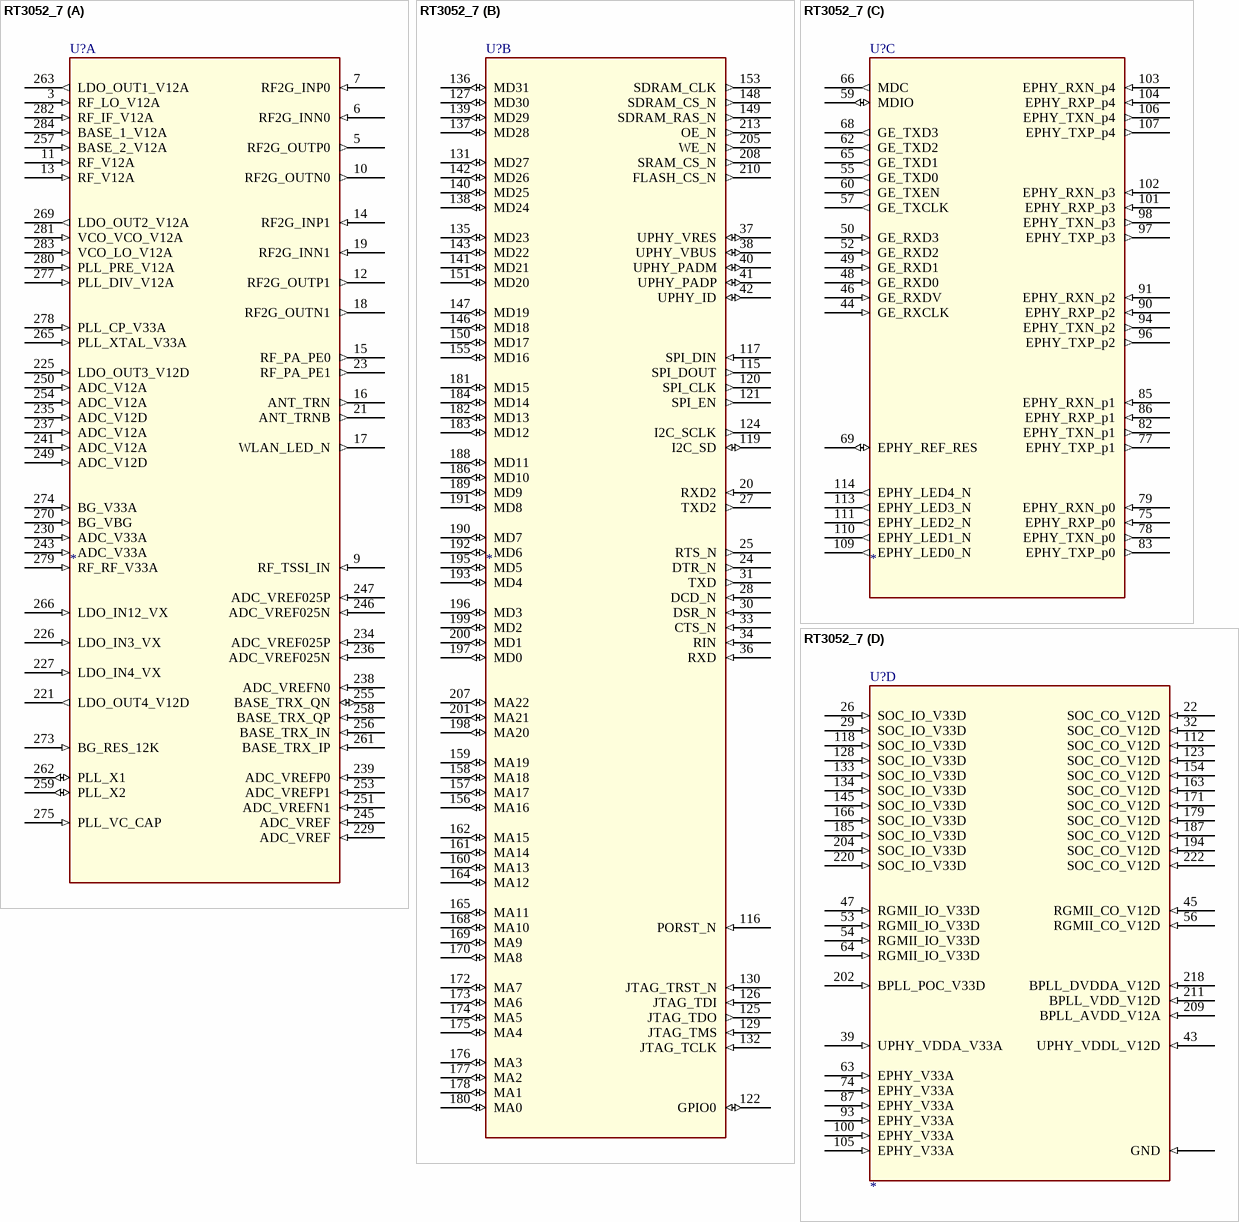
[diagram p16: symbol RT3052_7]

## RT3052_7
designator U?
footprint QFN285
part A pins: 3 RF_LO_V12A (in), 5 RF2G_OUTP0 (out), 6 RF2G_INN0 (in), 7 RF2G_INP0 (in), 9 RF_TSSI_IN (in), 10 RF2G_OUTN0 (out), 11 RF_V12A (in), 12 RF2G_OUTP1 (out), 13 RF_V12A (in), 14 RF2G_INP1 (in), 15 RF_PA_PE0 (out), 16 ANT_TRN (out), 17 WLAN_LED_N (out), 18 RF2G_OUTN1 (out), 19 RF2G_INN1 (in), 21 ANT_TRNB (out), 23 RF_PA_PE1 (out), 221 LDO_OUT4_V12D (out), 225 LDO_OUT3_V12D (in), 226 LDO_IN3_VX (in), 227 LDO_IN4_VX (in), 229 ADC_VREF (in), 230 ADC_V33A (in), 234 ADC_VREF025P (in), 235 ADC_V12D (in), 236 ADC_VREF025N (in), 237 ADC_V12A (in), 238 ADC_VREFN0 (in), 239 ADC_VREFP0 (in), 241 ADC_V12A (in), 243 ADC_V33A (in), 245 ADC_VREF (in), 246 ADC_VREF025N (in), 247 ADC_VREF025P (in), 249 ADC_V12D (in), 250 ADC_V12A (in), 251 ADC_VREFN1 (in), 253 ADC_VREFP1 (in), 254 ADC_V12A (in), 255 BASE_TRX_QN (io), 256 BASE_TRX_IN (in), 257 BASE_2_V12A (in), 258 BASE_TRX_QP (in), 259 PLL_X2 (io), 261 BASE_TRX_IP (in), 262 PLL_X1 (io), 263 LDO_OUT1_V12A (out), 265 PLL_XTAL_V33A (in), 266 LDO_IN12_VX (in), 269 LDO_OUT2_V12A (out), 270 BG_VBG (in), 273 BG_RES_12K (in), 274 BG_V33A (in), 275 PLL_VC_CAP (in), 277 PLL_DIV_V12A (in), 278 PLL_CP_V33A (in), 279 RF_RF_V33A (in), 280 PLL_PRE_V12A (in), 281 VCO_VCO_V12A (in), 282 RF_IF_V12A (in), 283 VCO_LO_V12A (in), 284 BASE_1_V12A (in)
part B pins: 20 RXD2 (in), 24 DTR_N (out), 25 RTS_N (out), 27 TXD2 (out), 28 DCD_N (in), 30 DSR_N (in), 31 TXD (out), 33 CTS_N (in), 34 RIN (in), 36 RXD (in), 37 UPHY_VRES (io), 38 UPHY_VBUS (io), 40 UPHY_PADM (io), 41 UPHY_PADP (io), 42 UPHY_ID (io), 115 SPI_DOUT (out), 116 PORST_N (in), 117 SPI_DIN (in), 119 I2C_SD (io), 120 SPI_CLK (out), 121 SPI_EN (out), 122 GPIO0 (io), 124 I2C_SCLK (out), 125 JTAG_TDO (out), 126 JTAG_TDI (in), 127 MD30 (io), 129 JTAG_TMS (in), 130 JTAG_TRST_N (in), 131 MD27 (io), 132 JTAG_TCLK (in), 135 MD23 (io), 136 MD31 (io), 137 MD28 (io), 138 MD24 (io), 139 MD29 (io), 140 MD25 (io), 141 MD21 (io), 142 MD26 (io), 143 MD22 (io), 146 MD18 (io), 147 MD19 (io), 148 SDRAM_CS_N (out), 149 SDRAM_RAS_N (out), 150 MD17 (io), 151 MD20 (io), 153 SDRAM_CLK (out), 155 MD16 (io), 156 MA16 (io), 157 MA17 (io), 158 MA18 (io), 159 MA19 (io), 160 MA13 (io), 161 MA14 (io), 162 MA15 (io), 164 MA12 (io), 165 MA11 (io), 168 MA10 (io), 169 MA9 (io), 170 MA8 (io), 172 MA7 (io), 173 MA6 (io), 174 MA5 (io), 175 MA4 (io), 176 MA3 (io), 177 MA2 (io), 178 MA1 (io), 180 MA0 (io), 181 MD15 (io), 182 MD13 (io), 183 MD12 (io), 184 MD14 (io), 186 MD10 (io), 188 MD11 (io), 189 MD9 (io), 190 MD7 (io), 191 MD8 (io), 192 MD6 (io), 193 MD4 (io), 195 MD5 (io), 196 MD3 (io), 197 MD0 (io), 198 MA20 (io), 199 MD2 (io), 200 MD1 (io), 201 MA21 (io), 205 WE_N (out), 207 MA22 (io), 208 SRAM_CS_N (out), 210 FLASH_CS_N (out), 213 OE_N (out)
part C pins: 44 GE_RXCLK (in), 46 GE_RXDV (in), 48 GE_RXD0 (in), 49 GE_RXD1 (in), 50 GE_RXD3 (in), 52 GE_RXD2 (in), 55 GE_TXD0 (out), 57 GE_TXCLK (out), 59 MDIO (io), 60 GE_TXEN (out), 62 GE_TXD2 (out), 65 GE_TXD1 (out), 66 MDC (out), 68 GE_TXD3 (out), 69 EPHY_REF_RES (io), 75 EPHY_RXP_p0 (in), 77 EPHY_TXP_p1 (out), 78 EPHY_TXN_p0 (out), 79 EPHY_RXN_p0 (in), 82 EPHY_TXN_p1 (out), 83 EPHY_TXP_p0 (out), 85 EPHY_RXN_p1 (in), 86 EPHY_RXP_p1 (in), 90 EPHY_RXP_p2 (in), 91 EPHY_RXN_p2 (in), 94 EPHY_TXN_p2 (out), 96 EPHY_TXP_p2 (out), 97 EPHY_TXP_p3 (out), 98 EPHY_TXN_p3 (out), 101 EPHY_RXP_p3 (in), 102 EPHY_RXN_p3 (in), 103 EPHY_RXN_p4 (in), 104 EPHY_RXP_p4 (in), 106 EPHY_TXN_p4 (out), 107 EPHY_TXP_p4 (out), 109 EPHY_LED0_N (out), 110 EPHY_LED1_N (out), 111 EPHY_LED2_N (out), 113 EPHY_LED3_N (out), 114 EPHY_LED4_N (out)
part D pins: 22 SOC_CO_V12D (in), 26 SOC_IO_V33D (in), 29 SOC_IO_V33D (in), 32 SOC_CO_V12D (in), 39 UPHY_VDDA_V33A (in), 43 UPHY_VDDL_V12D (in), 45 RGMII_CO_V12D (in), 47 RGMII_IO_V33D (in), 53 RGMII_IO_V33D (in), 54 RGMII_IO_V33D (in), 56 RGMII_CO_V12D (in), 63 EPHY_V33A (in), 64 RGMII_IO_V33D (in), 74 EPHY_V33A (in), 87 EPHY_V33A (in), 93 EPHY_V33A (in), 100 EPHY_V33A (in), 105 EPHY_V33A (in), 112 SOC_CO_V12D (in), 118 SOC_IO_V33D (in), 123 SOC_CO_V12D (in), 128 SOC_IO_V33D (in), 133 SOC_IO_V33D (in), 134 SOC_IO_V33D (in), 145 SOC_IO_V33D (in), 154 SOC_CO_V12D (in), 163 SOC_CO_V12D (in), 166 SOC_IO_V33D (in), 171 SOC_CO_V12D (in), 179 SOC_CO_V12D (in), 185 SOC_IO_V33D (in), 187 SOC_CO_V12D (in), 194 SOC_CO_V12D (in), 202 BPLL_POC_V33D (in), 204 SOC_IO_V33D (in), 209 BPLL_AVDD_V12A (in), 211 BPLL_VDD_V12D (in), 218 BPLL_DVDDA_V12D (in), 220 SOC_IO_V33D (in), 222 SOC_CO_V12D (in), GND (in)

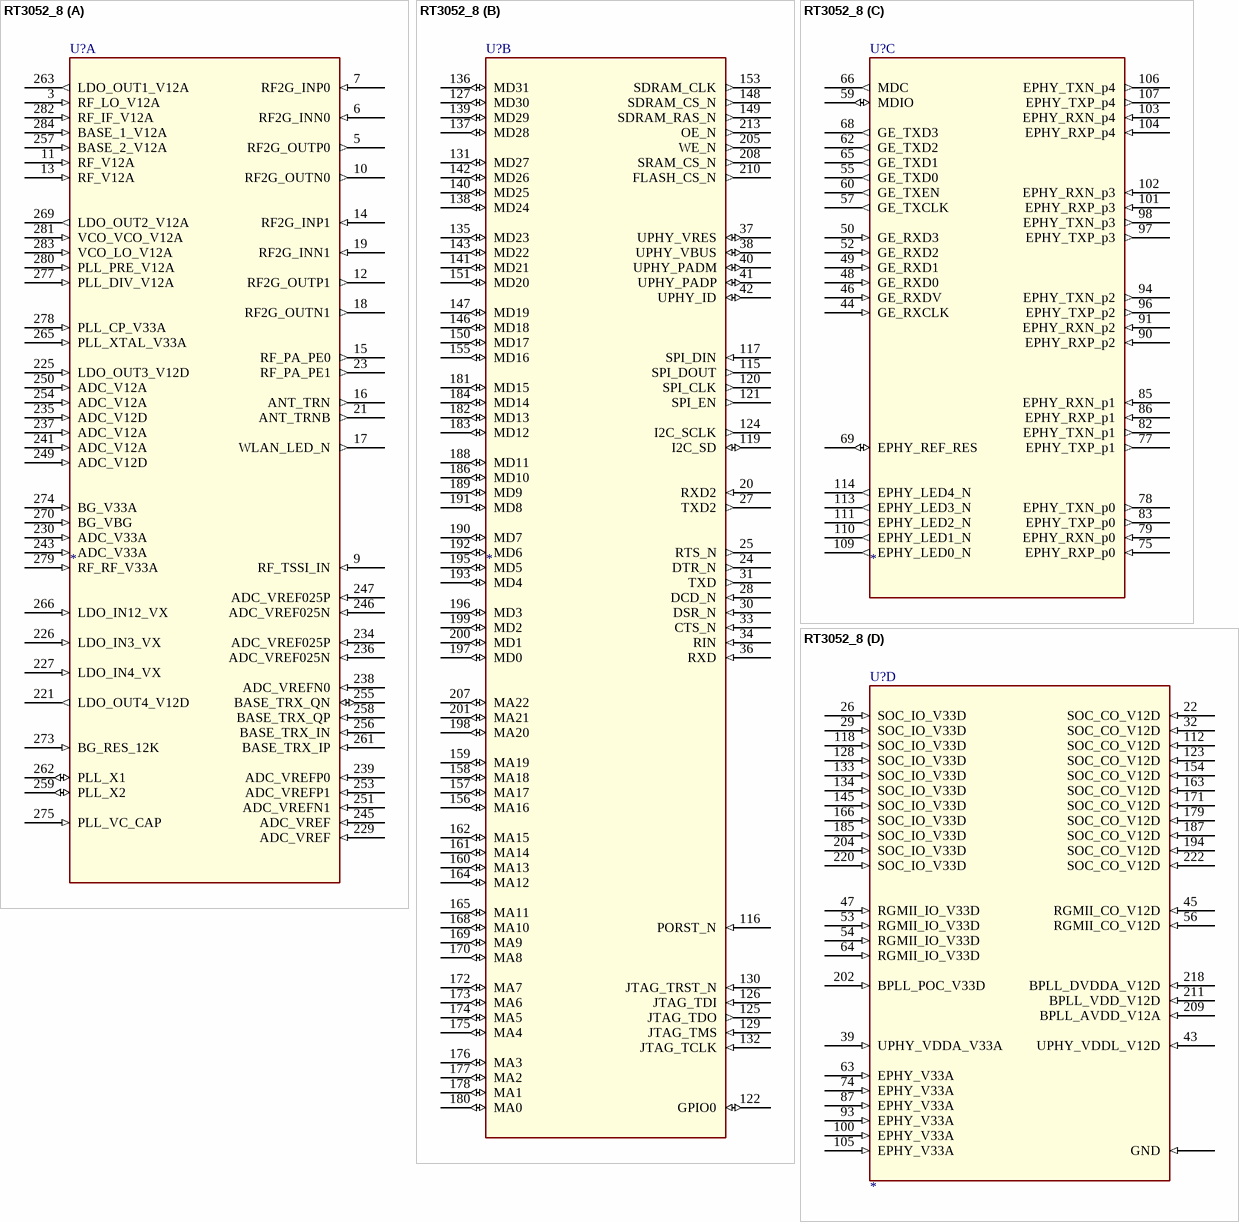
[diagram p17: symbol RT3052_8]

## RT3052_8
designator U?
footprint QFN285
part A pins: 3 RF_LO_V12A (in), 5 RF2G_OUTP0 (out), 6 RF2G_INN0 (in), 7 RF2G_INP0 (in), 9 RF_TSSI_IN (in), 10 RF2G_OUTN0 (out), 11 RF_V12A (in), 12 RF2G_OUTP1 (out), 13 RF_V12A (in), 14 RF2G_INP1 (in), 15 RF_PA_PE0 (out), 16 ANT_TRN (out), 17 WLAN_LED_N (out), 18 RF2G_OUTN1 (out), 19 RF2G_INN1 (in), 21 ANT_TRNB (out), 23 RF_PA_PE1 (out), 221 LDO_OUT4_V12D (out), 225 LDO_OUT3_V12D (in), 226 LDO_IN3_VX (in), 227 LDO_IN4_VX (in), 229 ADC_VREF (in), 230 ADC_V33A (in), 234 ADC_VREF025P (in), 235 ADC_V12D (in), 236 ADC_VREF025N (in), 237 ADC_V12A (in), 238 ADC_VREFN0 (in), 239 ADC_VREFP0 (in), 241 ADC_V12A (in), 243 ADC_V33A (in), 245 ADC_VREF (in), 246 ADC_VREF025N (in), 247 ADC_VREF025P (in), 249 ADC_V12D (in), 250 ADC_V12A (in), 251 ADC_VREFN1 (in), 253 ADC_VREFP1 (in), 254 ADC_V12A (in), 255 BASE_TRX_QN (io), 256 BASE_TRX_IN (in), 257 BASE_2_V12A (in), 258 BASE_TRX_QP (in), 259 PLL_X2 (io), 261 BASE_TRX_IP (in), 262 PLL_X1 (io), 263 LDO_OUT1_V12A (out), 265 PLL_XTAL_V33A (in), 266 LDO_IN12_VX (in), 269 LDO_OUT2_V12A (out), 270 BG_VBG (in), 273 BG_RES_12K (in), 274 BG_V33A (in), 275 PLL_VC_CAP (in), 277 PLL_DIV_V12A (in), 278 PLL_CP_V33A (in), 279 RF_RF_V33A (in), 280 PLL_PRE_V12A (in), 281 VCO_VCO_V12A (in), 282 RF_IF_V12A (in), 283 VCO_LO_V12A (in), 284 BASE_1_V12A (in)
part B pins: 20 RXD2 (in), 24 DTR_N (out), 25 RTS_N (out), 27 TXD2 (out), 28 DCD_N (in), 30 DSR_N (in), 31 TXD (out), 33 CTS_N (in), 34 RIN (in), 36 RXD (in), 37 UPHY_VRES (io), 38 UPHY_VBUS (io), 40 UPHY_PADM (io), 41 UPHY_PADP (io), 42 UPHY_ID (io), 115 SPI_DOUT (out), 116 PORST_N (in), 117 SPI_DIN (in), 119 I2C_SD (io), 120 SPI_CLK (out), 121 SPI_EN (out), 122 GPIO0 (io), 124 I2C_SCLK (out), 125 JTAG_TDO (out), 126 JTAG_TDI (in), 127 MD30 (io), 129 JTAG_TMS (in), 130 JTAG_TRST_N (in), 131 MD27 (io), 132 JTAG_TCLK (in), 135 MD23 (io), 136 MD31 (io), 137 MD28 (io), 138 MD24 (io), 139 MD29 (io), 140 MD25 (io), 141 MD21 (io), 142 MD26 (io), 143 MD22 (io), 146 MD18 (io), 147 MD19 (io), 148 SDRAM_CS_N (out), 149 SDRAM_RAS_N (out), 150 MD17 (io), 151 MD20 (io), 153 SDRAM_CLK (out), 155 MD16 (io), 156 MA16 (io), 157 MA17 (io), 158 MA18 (io), 159 MA19 (io), 160 MA13 (io), 161 MA14 (io), 162 MA15 (io), 164 MA12 (io), 165 MA11 (io), 168 MA10 (io), 169 MA9 (io), 170 MA8 (io), 172 MA7 (io), 173 MA6 (io), 174 MA5 (io), 175 MA4 (io), 176 MA3 (io), 177 MA2 (io), 178 MA1 (io), 180 MA0 (io), 181 MD15 (io), 182 MD13 (io), 183 MD12 (io), 184 MD14 (io), 186 MD10 (io), 188 MD11 (io), 189 MD9 (io), 190 MD7 (io), 191 MD8 (io), 192 MD6 (io), 193 MD4 (io), 195 MD5 (io), 196 MD3 (io), 197 MD0 (io), 198 MA20 (io), 199 MD2 (io), 200 MD1 (io), 201 MA21 (io), 205 WE_N (out), 207 MA22 (io), 208 SRAM_CS_N (out), 210 FLASH_CS_N (out), 213 OE_N (out)
part C pins: 44 GE_RXCLK (in), 46 GE_RXDV (in), 48 GE_RXD0 (in), 49 GE_RXD1 (in), 50 GE_RXD3 (in), 52 GE_RXD2 (in), 55 GE_TXD0 (out), 57 GE_TXCLK (out), 59 MDIO (io), 60 GE_TXEN (out), 62 GE_TXD2 (out), 65 GE_TXD1 (out), 66 MDC (out), 68 GE_TXD3 (out), 69 EPHY_REF_RES (io), 75 EPHY_RXP_p0 (in), 77 EPHY_TXP_p1 (out), 78 EPHY_TXN_p0 (out), 79 EPHY_RXN_p0 (in), 82 EPHY_TXN_p1 (out), 83 EPHY_TXP_p0 (out), 85 EPHY_RXN_p1 (in), 86 EPHY_RXP_p1 (in), 90 EPHY_RXP_p2 (in), 91 EPHY_RXN_p2 (in), 94 EPHY_TXN_p2 (out), 96 EPHY_TXP_p2 (out), 97 EPHY_TXP_p3 (out), 98 EPHY_TXN_p3 (out), 101 EPHY_RXP_p3 (in), 102 EPHY_RXN_p3 (in), 103 EPHY_RXN_p4 (in), 104 EPHY_RXP_p4 (in), 106 EPHY_TXN_p4 (out), 107 EPHY_TXP_p4 (out), 109 EPHY_LED0_N (out), 110 EPHY_LED1_N (out), 111 EPHY_LED2_N (out), 113 EPHY_LED3_N (out), 114 EPHY_LED4_N (out)
part D pins: 22 SOC_CO_V12D (in), 26 SOC_IO_V33D (in), 29 SOC_IO_V33D (in), 32 SOC_CO_V12D (in), 39 UPHY_VDDA_V33A (in), 43 UPHY_VDDL_V12D (in), 45 RGMII_CO_V12D (in), 47 RGMII_IO_V33D (in), 53 RGMII_IO_V33D (in), 54 RGMII_IO_V33D (in), 56 RGMII_CO_V12D (in), 63 EPHY_V33A (in), 64 RGMII_IO_V33D (in), 74 EPHY_V33A (in), 87 EPHY_V33A (in), 93 EPHY_V33A (in), 100 EPHY_V33A (in), 105 EPHY_V33A (in), 112 SOC_CO_V12D (in), 118 SOC_IO_V33D (in), 123 SOC_CO_V12D (in), 128 SOC_IO_V33D (in), 133 SOC_IO_V33D (in), 134 SOC_IO_V33D (in), 145 SOC_IO_V33D (in), 154 SOC_CO_V12D (in), 163 SOC_CO_V12D (in), 166 SOC_IO_V33D (in), 171 SOC_CO_V12D (in), 179 SOC_CO_V12D (in), 185 SOC_IO_V33D (in), 187 SOC_CO_V12D (in), 194 SOC_CO_V12D (in), 202 BPLL_POC_V33D (in), 204 SOC_IO_V33D (in), 209 BPLL_AVDD_V12A (in), 211 BPLL_VDD_V12D (in), 218 BPLL_DVDDA_V12D (in), 220 SOC_IO_V33D (in), 222 SOC_CO_V12D (in), GND (in)

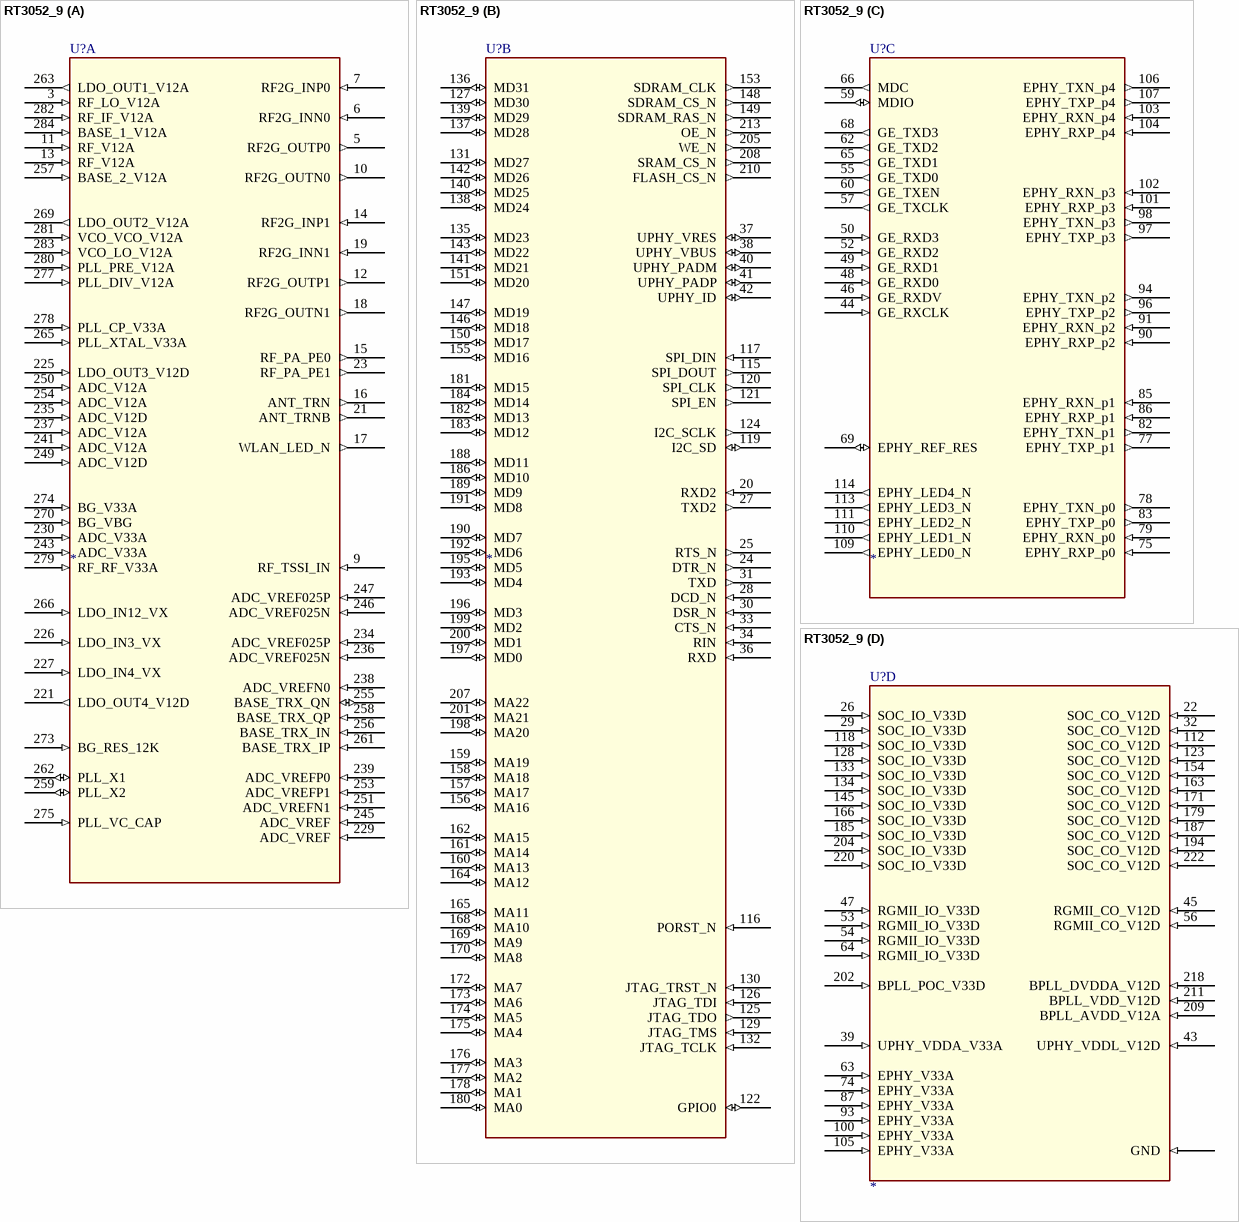
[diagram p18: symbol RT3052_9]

## RT3052_9
designator U?
footprint QFN285
part A pins: 3 RF_LO_V12A (in), 5 RF2G_OUTP0 (out), 6 RF2G_INN0 (in), 7 RF2G_INP0 (in), 9 RF_TSSI_IN (in), 10 RF2G_OUTN0 (out), 11 RF_V12A (in), 12 RF2G_OUTP1 (out), 13 RF_V12A (in), 14 RF2G_INP1 (in), 15 RF_PA_PE0 (out), 16 ANT_TRN (out), 17 WLAN_LED_N (out), 18 RF2G_OUTN1 (out), 19 RF2G_INN1 (in), 21 ANT_TRNB (out), 23 RF_PA_PE1 (out), 221 LDO_OUT4_V12D (out), 225 LDO_OUT3_V12D (in), 226 LDO_IN3_VX (in), 227 LDO_IN4_VX (in), 229 ADC_VREF (in), 230 ADC_V33A (in), 234 ADC_VREF025P (in), 235 ADC_V12D (in), 236 ADC_VREF025N (in), 237 ADC_V12A (in), 238 ADC_VREFN0 (in), 239 ADC_VREFP0 (in), 241 ADC_V12A (in), 243 ADC_V33A (in), 245 ADC_VREF (in), 246 ADC_VREF025N (in), 247 ADC_VREF025P (in), 249 ADC_V12D (in), 250 ADC_V12A (in), 251 ADC_VREFN1 (in), 253 ADC_VREFP1 (in), 254 ADC_V12A (in), 255 BASE_TRX_QN (io), 256 BASE_TRX_IN (in), 257 BASE_2_V12A (in), 258 BASE_TRX_QP (in), 259 PLL_X2 (io), 261 BASE_TRX_IP (in), 262 PLL_X1 (io), 263 LDO_OUT1_V12A (out), 265 PLL_XTAL_V33A (in), 266 LDO_IN12_VX (in), 269 LDO_OUT2_V12A (out), 270 BG_VBG (in), 273 BG_RES_12K (in), 274 BG_V33A (in), 275 PLL_VC_CAP (in), 277 PLL_DIV_V12A (in), 278 PLL_CP_V33A (in), 279 RF_RF_V33A (in), 280 PLL_PRE_V12A (in), 281 VCO_VCO_V12A (in), 282 RF_IF_V12A (in), 283 VCO_LO_V12A (in), 284 BASE_1_V12A (in)
part B pins: 20 RXD2 (in), 24 DTR_N (out), 25 RTS_N (out), 27 TXD2 (out), 28 DCD_N (in), 30 DSR_N (in), 31 TXD (out), 33 CTS_N (in), 34 RIN (in), 36 RXD (in), 37 UPHY_VRES (io), 38 UPHY_VBUS (io), 40 UPHY_PADM (io), 41 UPHY_PADP (io), 42 UPHY_ID (io), 115 SPI_DOUT (out), 116 PORST_N (in), 117 SPI_DIN (in), 119 I2C_SD (io), 120 SPI_CLK (out), 121 SPI_EN (out), 122 GPIO0 (io), 124 I2C_SCLK (out), 125 JTAG_TDO (out), 126 JTAG_TDI (in), 127 MD30 (io), 129 JTAG_TMS (in), 130 JTAG_TRST_N (in), 131 MD27 (io), 132 JTAG_TCLK (in), 135 MD23 (io), 136 MD31 (io), 137 MD28 (io), 138 MD24 (io), 139 MD29 (io), 140 MD25 (io), 141 MD21 (io), 142 MD26 (io), 143 MD22 (io), 146 MD18 (io), 147 MD19 (io), 148 SDRAM_CS_N (out), 149 SDRAM_RAS_N (out), 150 MD17 (io), 151 MD20 (io), 153 SDRAM_CLK (out), 155 MD16 (io), 156 MA16 (io), 157 MA17 (io), 158 MA18 (io), 159 MA19 (io), 160 MA13 (io), 161 MA14 (io), 162 MA15 (io), 164 MA12 (io), 165 MA11 (io), 168 MA10 (io), 169 MA9 (io), 170 MA8 (io), 172 MA7 (io), 173 MA6 (io), 174 MA5 (io), 175 MA4 (io), 176 MA3 (io), 177 MA2 (io), 178 MA1 (io), 180 MA0 (io), 181 MD15 (io), 182 MD13 (io), 183 MD12 (io), 184 MD14 (io), 186 MD10 (io), 188 MD11 (io), 189 MD9 (io), 190 MD7 (io), 191 MD8 (io), 192 MD6 (io), 193 MD4 (io), 195 MD5 (io), 196 MD3 (io), 197 MD0 (io), 198 MA20 (io), 199 MD2 (io), 200 MD1 (io), 201 MA21 (io), 205 WE_N (out), 207 MA22 (io), 208 SRAM_CS_N (out), 210 FLASH_CS_N (out), 213 OE_N (out)
part C pins: 44 GE_RXCLK (in), 46 GE_RXDV (in), 48 GE_RXD0 (in), 49 GE_RXD1 (in), 50 GE_RXD3 (in), 52 GE_RXD2 (in), 55 GE_TXD0 (out), 57 GE_TXCLK (out), 59 MDIO (io), 60 GE_TXEN (out), 62 GE_TXD2 (out), 65 GE_TXD1 (out), 66 MDC (out), 68 GE_TXD3 (out), 69 EPHY_REF_RES (io), 75 EPHY_RXP_p0 (in), 77 EPHY_TXP_p1 (out), 78 EPHY_TXN_p0 (out), 79 EPHY_RXN_p0 (in), 82 EPHY_TXN_p1 (out), 83 EPHY_TXP_p0 (out), 85 EPHY_RXN_p1 (in), 86 EPHY_RXP_p1 (in), 90 EPHY_RXP_p2 (in), 91 EPHY_RXN_p2 (in), 94 EPHY_TXN_p2 (out), 96 EPHY_TXP_p2 (out), 97 EPHY_TXP_p3 (out), 98 EPHY_TXN_p3 (out), 101 EPHY_RXP_p3 (in), 102 EPHY_RXN_p3 (in), 103 EPHY_RXN_p4 (in), 104 EPHY_RXP_p4 (in), 106 EPHY_TXN_p4 (out), 107 EPHY_TXP_p4 (out), 109 EPHY_LED0_N (out), 110 EPHY_LED1_N (out), 111 EPHY_LED2_N (out), 113 EPHY_LED3_N (out), 114 EPHY_LED4_N (out)
part D pins: 22 SOC_CO_V12D (in), 26 SOC_IO_V33D (in), 29 SOC_IO_V33D (in), 32 SOC_CO_V12D (in), 39 UPHY_VDDA_V33A (in), 43 UPHY_VDDL_V12D (in), 45 RGMII_CO_V12D (in), 47 RGMII_IO_V33D (in), 53 RGMII_IO_V33D (in), 54 RGMII_IO_V33D (in), 56 RGMII_CO_V12D (in), 63 EPHY_V33A (in), 64 RGMII_IO_V33D (in), 74 EPHY_V33A (in), 87 EPHY_V33A (in), 93 EPHY_V33A (in), 100 EPHY_V33A (in), 105 EPHY_V33A (in), 112 SOC_CO_V12D (in), 118 SOC_IO_V33D (in), 123 SOC_CO_V12D (in), 128 SOC_IO_V33D (in), 133 SOC_IO_V33D (in), 134 SOC_IO_V33D (in), 145 SOC_IO_V33D (in), 154 SOC_CO_V12D (in), 163 SOC_CO_V12D (in), 166 SOC_IO_V33D (in), 171 SOC_CO_V12D (in), 179 SOC_CO_V12D (in), 185 SOC_IO_V33D (in), 187 SOC_CO_V12D (in), 194 SOC_CO_V12D (in), 202 BPLL_POC_V33D (in), 204 SOC_IO_V33D (in), 209 BPLL_AVDD_V12A (in), 211 BPLL_VDD_V12D (in), 218 BPLL_DVDDA_V12D (in), 220 SOC_IO_V33D (in), 222 SOC_CO_V12D (in), GND (in)

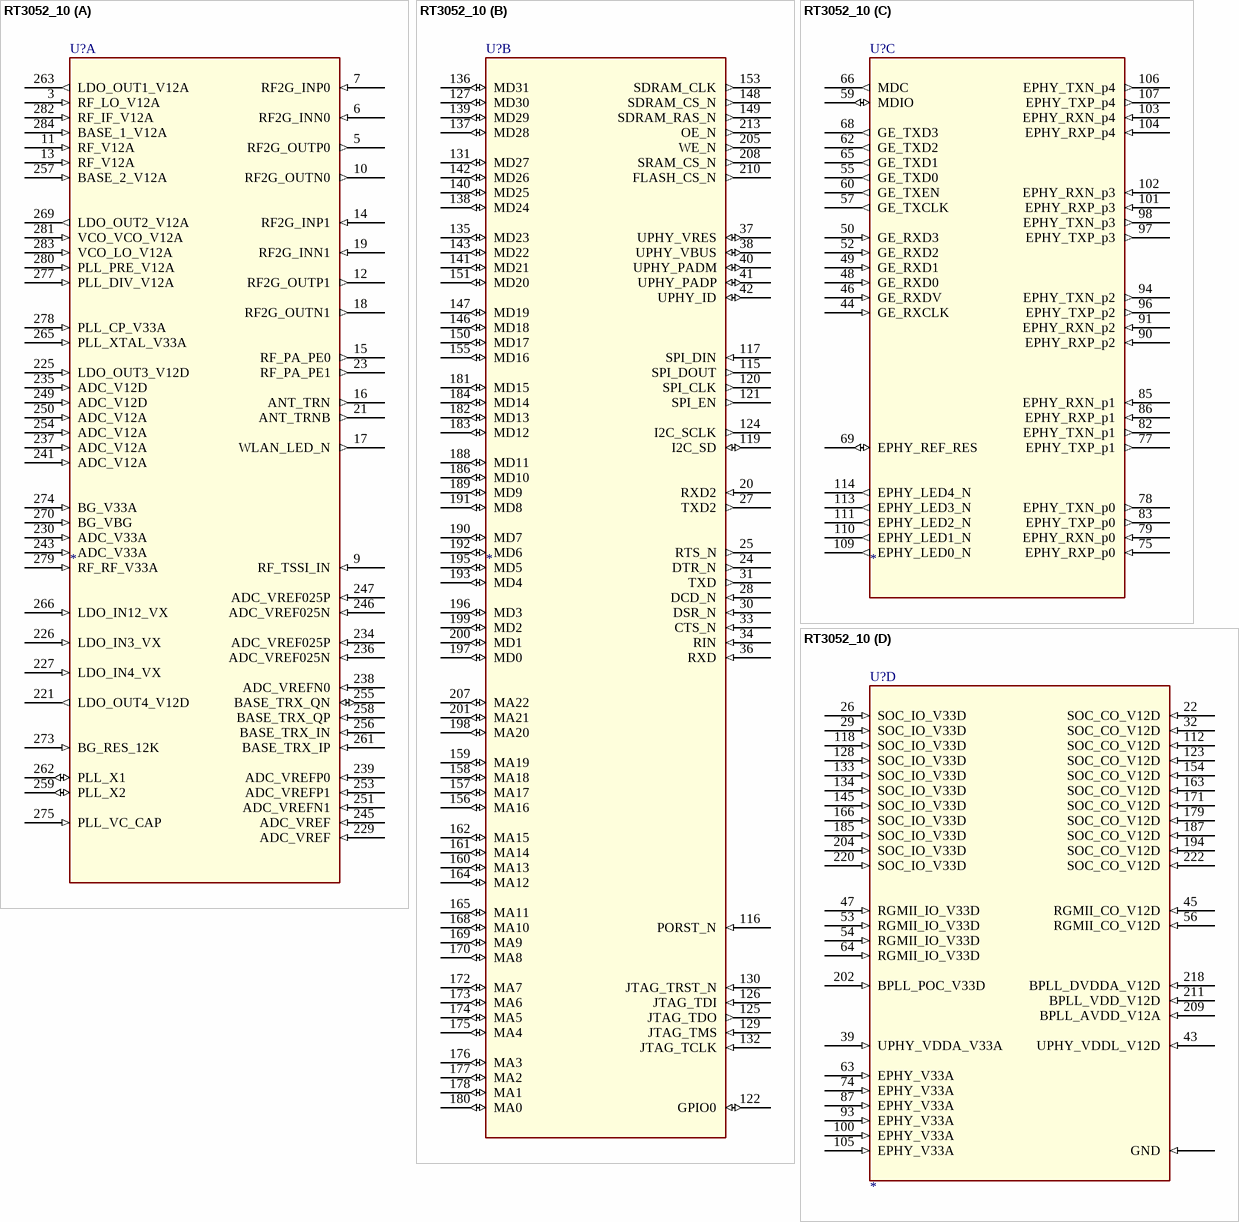
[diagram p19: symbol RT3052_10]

## RT3052_10
designator U?
footprint QFN285
part A pins: 3 RF_LO_V12A (in), 5 RF2G_OUTP0 (out), 6 RF2G_INN0 (in), 7 RF2G_INP0 (in), 9 RF_TSSI_IN (in), 10 RF2G_OUTN0 (out), 11 RF_V12A (in), 12 RF2G_OUTP1 (out), 13 RF_V12A (in), 14 RF2G_INP1 (in), 15 RF_PA_PE0 (out), 16 ANT_TRN (out), 17 WLAN_LED_N (out), 18 RF2G_OUTN1 (out), 19 RF2G_INN1 (in), 21 ANT_TRNB (out), 23 RF_PA_PE1 (out), 221 LDO_OUT4_V12D (out), 225 LDO_OUT3_V12D (in), 226 LDO_IN3_VX (in), 227 LDO_IN4_VX (in), 229 ADC_VREF (in), 230 ADC_V33A (in), 234 ADC_VREF025P (in), 235 ADC_V12D (in), 236 ADC_VREF025N (in), 237 ADC_V12A (in), 238 ADC_VREFN0 (in), 239 ADC_VREFP0 (in), 241 ADC_V12A (in), 243 ADC_V33A (in), 245 ADC_VREF (in), 246 ADC_VREF025N (in), 247 ADC_VREF025P (in), 249 ADC_V12D (in), 250 ADC_V12A (in), 251 ADC_VREFN1 (in), 253 ADC_VREFP1 (in), 254 ADC_V12A (in), 255 BASE_TRX_QN (io), 256 BASE_TRX_IN (in), 257 BASE_2_V12A (in), 258 BASE_TRX_QP (in), 259 PLL_X2 (io), 261 BASE_TRX_IP (in), 262 PLL_X1 (io), 263 LDO_OUT1_V12A (out), 265 PLL_XTAL_V33A (in), 266 LDO_IN12_VX (in), 269 LDO_OUT2_V12A (out), 270 BG_VBG (in), 273 BG_RES_12K (in), 274 BG_V33A (in), 275 PLL_VC_CAP (in), 277 PLL_DIV_V12A (in), 278 PLL_CP_V33A (in), 279 RF_RF_V33A (in), 280 PLL_PRE_V12A (in), 281 VCO_VCO_V12A (in), 282 RF_IF_V12A (in), 283 VCO_LO_V12A (in), 284 BASE_1_V12A (in)
part B pins: 20 RXD2 (in), 24 DTR_N (out), 25 RTS_N (out), 27 TXD2 (out), 28 DCD_N (in), 30 DSR_N (in), 31 TXD (out), 33 CTS_N (in), 34 RIN (in), 36 RXD (in), 37 UPHY_VRES (io), 38 UPHY_VBUS (io), 40 UPHY_PADM (io), 41 UPHY_PADP (io), 42 UPHY_ID (io), 115 SPI_DOUT (out), 116 PORST_N (in), 117 SPI_DIN (in), 119 I2C_SD (io), 120 SPI_CLK (out), 121 SPI_EN (out), 122 GPIO0 (io), 124 I2C_SCLK (out), 125 JTAG_TDO (out), 126 JTAG_TDI (in), 127 MD30 (io), 129 JTAG_TMS (in), 130 JTAG_TRST_N (in), 131 MD27 (io), 132 JTAG_TCLK (in), 135 MD23 (io), 136 MD31 (io), 137 MD28 (io), 138 MD24 (io), 139 MD29 (io), 140 MD25 (io), 141 MD21 (io), 142 MD26 (io), 143 MD22 (io), 146 MD18 (io), 147 MD19 (io), 148 SDRAM_CS_N (out), 149 SDRAM_RAS_N (out), 150 MD17 (io), 151 MD20 (io), 153 SDRAM_CLK (out), 155 MD16 (io), 156 MA16 (io), 157 MA17 (io), 158 MA18 (io), 159 MA19 (io), 160 MA13 (io), 161 MA14 (io), 162 MA15 (io), 164 MA12 (io), 165 MA11 (io), 168 MA10 (io), 169 MA9 (io), 170 MA8 (io), 172 MA7 (io), 173 MA6 (io), 174 MA5 (io), 175 MA4 (io), 176 MA3 (io), 177 MA2 (io), 178 MA1 (io), 180 MA0 (io), 181 MD15 (io), 182 MD13 (io), 183 MD12 (io), 184 MD14 (io), 186 MD10 (io), 188 MD11 (io), 189 MD9 (io), 190 MD7 (io), 191 MD8 (io), 192 MD6 (io), 193 MD4 (io), 195 MD5 (io), 196 MD3 (io), 197 MD0 (io), 198 MA20 (io), 199 MD2 (io), 200 MD1 (io), 201 MA21 (io), 205 WE_N (out), 207 MA22 (io), 208 SRAM_CS_N (out), 210 FLASH_CS_N (out), 213 OE_N (out)
part C pins: 44 GE_RXCLK (in), 46 GE_RXDV (in), 48 GE_RXD0 (in), 49 GE_RXD1 (in), 50 GE_RXD3 (in), 52 GE_RXD2 (in), 55 GE_TXD0 (out), 57 GE_TXCLK (out), 59 MDIO (io), 60 GE_TXEN (out), 62 GE_TXD2 (out), 65 GE_TXD1 (out), 66 MDC (out), 68 GE_TXD3 (out), 69 EPHY_REF_RES (io), 75 EPHY_RXP_p0 (in), 77 EPHY_TXP_p1 (out), 78 EPHY_TXN_p0 (out), 79 EPHY_RXN_p0 (in), 82 EPHY_TXN_p1 (out), 83 EPHY_TXP_p0 (out), 85 EPHY_RXN_p1 (in), 86 EPHY_RXP_p1 (in), 90 EPHY_RXP_p2 (in), 91 EPHY_RXN_p2 (in), 94 EPHY_TXN_p2 (out), 96 EPHY_TXP_p2 (out), 97 EPHY_TXP_p3 (out), 98 EPHY_TXN_p3 (out), 101 EPHY_RXP_p3 (in), 102 EPHY_RXN_p3 (in), 103 EPHY_RXN_p4 (in), 104 EPHY_RXP_p4 (in), 106 EPHY_TXN_p4 (out), 107 EPHY_TXP_p4 (out), 109 EPHY_LED0_N (out), 110 EPHY_LED1_N (out), 111 EPHY_LED2_N (out), 113 EPHY_LED3_N (out), 114 EPHY_LED4_N (out)
part D pins: 22 SOC_CO_V12D (in), 26 SOC_IO_V33D (in), 29 SOC_IO_V33D (in), 32 SOC_CO_V12D (in), 39 UPHY_VDDA_V33A (in), 43 UPHY_VDDL_V12D (in), 45 RGMII_CO_V12D (in), 47 RGMII_IO_V33D (in), 53 RGMII_IO_V33D (in), 54 RGMII_IO_V33D (in), 56 RGMII_CO_V12D (in), 63 EPHY_V33A (in), 64 RGMII_IO_V33D (in), 74 EPHY_V33A (in), 87 EPHY_V33A (in), 93 EPHY_V33A (in), 100 EPHY_V33A (in), 105 EPHY_V33A (in), 112 SOC_CO_V12D (in), 118 SOC_IO_V33D (in), 123 SOC_CO_V12D (in), 128 SOC_IO_V33D (in), 133 SOC_IO_V33D (in), 134 SOC_IO_V33D (in), 145 SOC_IO_V33D (in), 154 SOC_CO_V12D (in), 163 SOC_CO_V12D (in), 166 SOC_IO_V33D (in), 171 SOC_CO_V12D (in), 179 SOC_CO_V12D (in), 185 SOC_IO_V33D (in), 187 SOC_CO_V12D (in), 194 SOC_CO_V12D (in), 202 BPLL_POC_V33D (in), 204 SOC_IO_V33D (in), 209 BPLL_AVDD_V12A (in), 211 BPLL_VDD_V12D (in), 218 BPLL_DVDDA_V12D (in), 220 SOC_IO_V33D (in), 222 SOC_CO_V12D (in), GND (in)

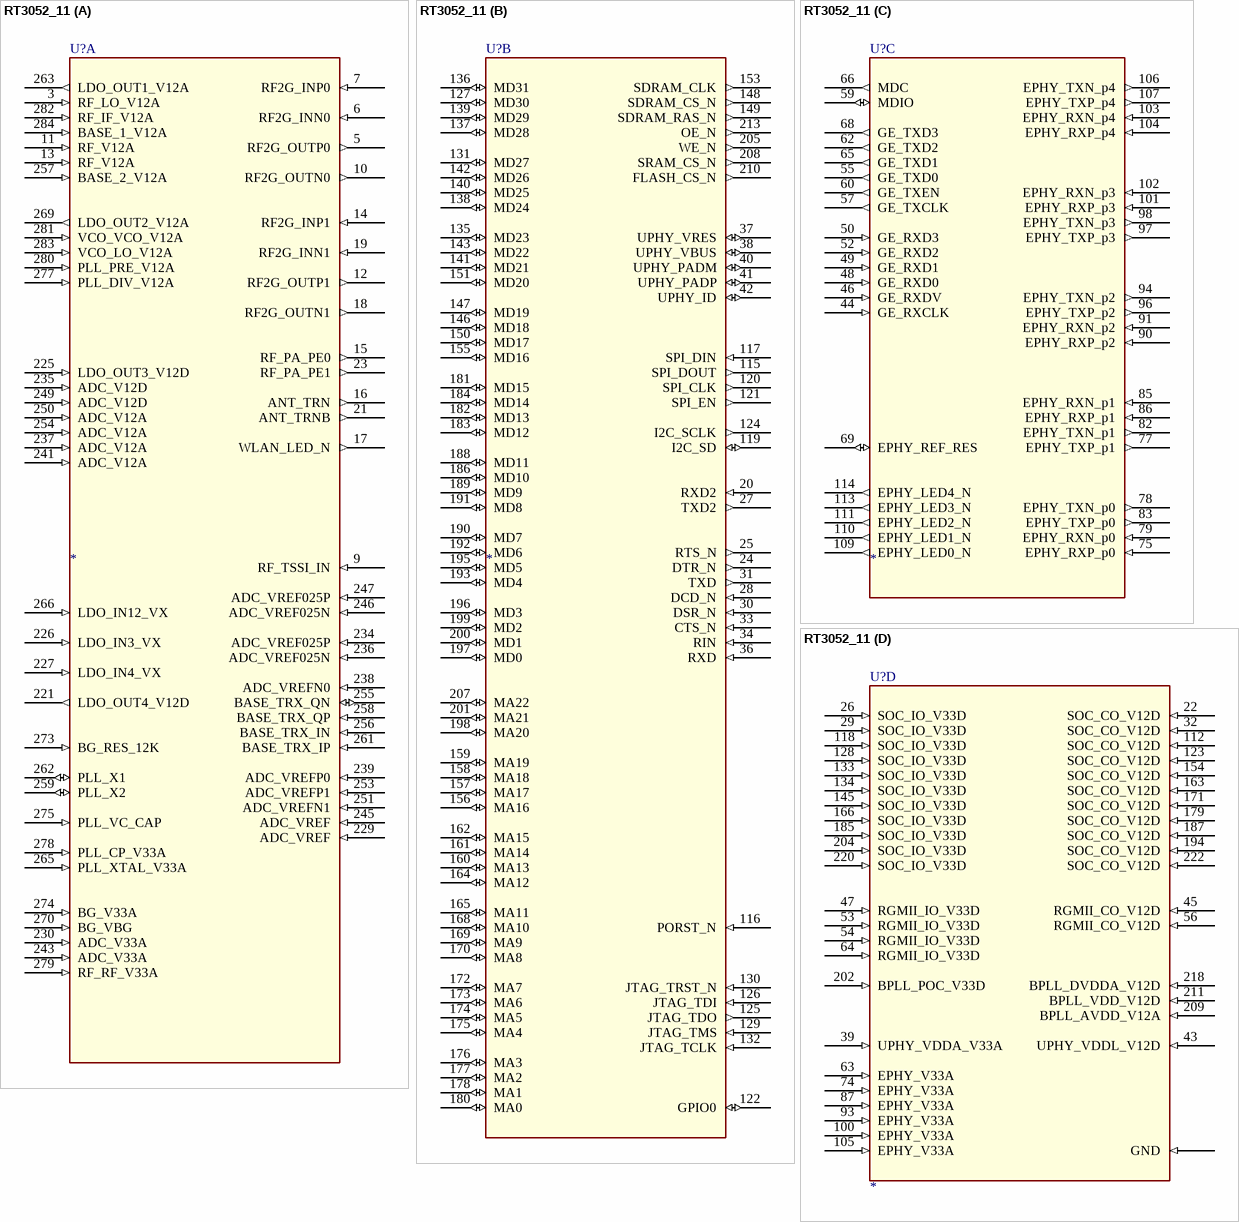
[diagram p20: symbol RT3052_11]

## RT3052_11
designator U?
footprint QFN285
part A pins: 3 RF_LO_V12A (in), 5 RF2G_OUTP0 (out), 6 RF2G_INN0 (in), 7 RF2G_INP0 (in), 9 RF_TSSI_IN (in), 10 RF2G_OUTN0 (out), 11 RF_V12A (in), 12 RF2G_OUTP1 (out), 13 RF_V12A (in), 14 RF2G_INP1 (in), 15 RF_PA_PE0 (out), 16 ANT_TRN (out), 17 WLAN_LED_N (out), 18 RF2G_OUTN1 (out), 19 RF2G_INN1 (in), 21 ANT_TRNB (out), 23 RF_PA_PE1 (out), 221 LDO_OUT4_V12D (out), 225 LDO_OUT3_V12D (in), 226 LDO_IN3_VX (in), 227 LDO_IN4_VX (in), 229 ADC_VREF (in), 230 ADC_V33A (in), 234 ADC_VREF025P (in), 235 ADC_V12D (in), 236 ADC_VREF025N (in), 237 ADC_V12A (in), 238 ADC_VREFN0 (in), 239 ADC_VREFP0 (in), 241 ADC_V12A (in), 243 ADC_V33A (in), 245 ADC_VREF (in), 246 ADC_VREF025N (in), 247 ADC_VREF025P (in), 249 ADC_V12D (in), 250 ADC_V12A (in), 251 ADC_VREFN1 (in), 253 ADC_VREFP1 (in), 254 ADC_V12A (in), 255 BASE_TRX_QN (io), 256 BASE_TRX_IN (in), 257 BASE_2_V12A (in), 258 BASE_TRX_QP (in), 259 PLL_X2 (io), 261 BASE_TRX_IP (in), 262 PLL_X1 (io), 263 LDO_OUT1_V12A (out), 265 PLL_XTAL_V33A (in), 266 LDO_IN12_VX (in), 269 LDO_OUT2_V12A (out), 270 BG_VBG (in), 273 BG_RES_12K (in), 274 BG_V33A (in), 275 PLL_VC_CAP (in), 277 PLL_DIV_V12A (in), 278 PLL_CP_V33A (in), 279 RF_RF_V33A (in), 280 PLL_PRE_V12A (in), 281 VCO_VCO_V12A (in), 282 RF_IF_V12A (in), 283 VCO_LO_V12A (in), 284 BASE_1_V12A (in)
part B pins: 20 RXD2 (in), 24 DTR_N (out), 25 RTS_N (out), 27 TXD2 (out), 28 DCD_N (in), 30 DSR_N (in), 31 TXD (out), 33 CTS_N (in), 34 RIN (in), 36 RXD (in), 37 UPHY_VRES (io), 38 UPHY_VBUS (io), 40 UPHY_PADM (io), 41 UPHY_PADP (io), 42 UPHY_ID (io), 115 SPI_DOUT (out), 116 PORST_N (in), 117 SPI_DIN (in), 119 I2C_SD (io), 120 SPI_CLK (out), 121 SPI_EN (out), 122 GPIO0 (io), 124 I2C_SCLK (out), 125 JTAG_TDO (out), 126 JTAG_TDI (in), 127 MD30 (io), 129 JTAG_TMS (in), 130 JTAG_TRST_N (in), 131 MD27 (io), 132 JTAG_TCLK (in), 135 MD23 (io), 136 MD31 (io), 137 MD28 (io), 138 MD24 (io), 139 MD29 (io), 140 MD25 (io), 141 MD21 (io), 142 MD26 (io), 143 MD22 (io), 146 MD18 (io), 147 MD19 (io), 148 SDRAM_CS_N (out), 149 SDRAM_RAS_N (out), 150 MD17 (io), 151 MD20 (io), 153 SDRAM_CLK (out), 155 MD16 (io), 156 MA16 (io), 157 MA17 (io), 158 MA18 (io), 159 MA19 (io), 160 MA13 (io), 161 MA14 (io), 162 MA15 (io), 164 MA12 (io), 165 MA11 (io), 168 MA10 (io), 169 MA9 (io), 170 MA8 (io), 172 MA7 (io), 173 MA6 (io), 174 MA5 (io), 175 MA4 (io), 176 MA3 (io), 177 MA2 (io), 178 MA1 (io), 180 MA0 (io), 181 MD15 (io), 182 MD13 (io), 183 MD12 (io), 184 MD14 (io), 186 MD10 (io), 188 MD11 (io), 189 MD9 (io), 190 MD7 (io), 191 MD8 (io), 192 MD6 (io), 193 MD4 (io), 195 MD5 (io), 196 MD3 (io), 197 MD0 (io), 198 MA20 (io), 199 MD2 (io), 200 MD1 (io), 201 MA21 (io), 205 WE_N (out), 207 MA22 (io), 208 SRAM_CS_N (out), 210 FLASH_CS_N (out), 213 OE_N (out)
part C pins: 44 GE_RXCLK (in), 46 GE_RXDV (in), 48 GE_RXD0 (in), 49 GE_RXD1 (in), 50 GE_RXD3 (in), 52 GE_RXD2 (in), 55 GE_TXD0 (out), 57 GE_TXCLK (out), 59 MDIO (io), 60 GE_TXEN (out), 62 GE_TXD2 (out), 65 GE_TXD1 (out), 66 MDC (out), 68 GE_TXD3 (out), 69 EPHY_REF_RES (io), 75 EPHY_RXP_p0 (in), 77 EPHY_TXP_p1 (out), 78 EPHY_TXN_p0 (out), 79 EPHY_RXN_p0 (in), 82 EPHY_TXN_p1 (out), 83 EPHY_TXP_p0 (out), 85 EPHY_RXN_p1 (in), 86 EPHY_RXP_p1 (in), 90 EPHY_RXP_p2 (in), 91 EPHY_RXN_p2 (in), 94 EPHY_TXN_p2 (out), 96 EPHY_TXP_p2 (out), 97 EPHY_TXP_p3 (out), 98 EPHY_TXN_p3 (out), 101 EPHY_RXP_p3 (in), 102 EPHY_RXN_p3 (in), 103 EPHY_RXN_p4 (in), 104 EPHY_RXP_p4 (in), 106 EPHY_TXN_p4 (out), 107 EPHY_TXP_p4 (out), 109 EPHY_LED0_N (out), 110 EPHY_LED1_N (out), 111 EPHY_LED2_N (out), 113 EPHY_LED3_N (out), 114 EPHY_LED4_N (out)
part D pins: 22 SOC_CO_V12D (in), 26 SOC_IO_V33D (in), 29 SOC_IO_V33D (in), 32 SOC_CO_V12D (in), 39 UPHY_VDDA_V33A (in), 43 UPHY_VDDL_V12D (in), 45 RGMII_CO_V12D (in), 47 RGMII_IO_V33D (in), 53 RGMII_IO_V33D (in), 54 RGMII_IO_V33D (in), 56 RGMII_CO_V12D (in), 63 EPHY_V33A (in), 64 RGMII_IO_V33D (in), 74 EPHY_V33A (in), 87 EPHY_V33A (in), 93 EPHY_V33A (in), 100 EPHY_V33A (in), 105 EPHY_V33A (in), 112 SOC_CO_V12D (in), 118 SOC_IO_V33D (in), 123 SOC_CO_V12D (in), 128 SOC_IO_V33D (in), 133 SOC_IO_V33D (in), 134 SOC_IO_V33D (in), 145 SOC_IO_V33D (in), 154 SOC_CO_V12D (in), 163 SOC_CO_V12D (in), 166 SOC_IO_V33D (in), 171 SOC_CO_V12D (in), 179 SOC_CO_V12D (in), 185 SOC_IO_V33D (in), 187 SOC_CO_V12D (in), 194 SOC_CO_V12D (in), 202 BPLL_POC_V33D (in), 204 SOC_IO_V33D (in), 209 BPLL_AVDD_V12A (in), 211 BPLL_VDD_V12D (in), 218 BPLL_DVDDA_V12D (in), 220 SOC_IO_V33D (in), 222 SOC_CO_V12D (in), GND (in)

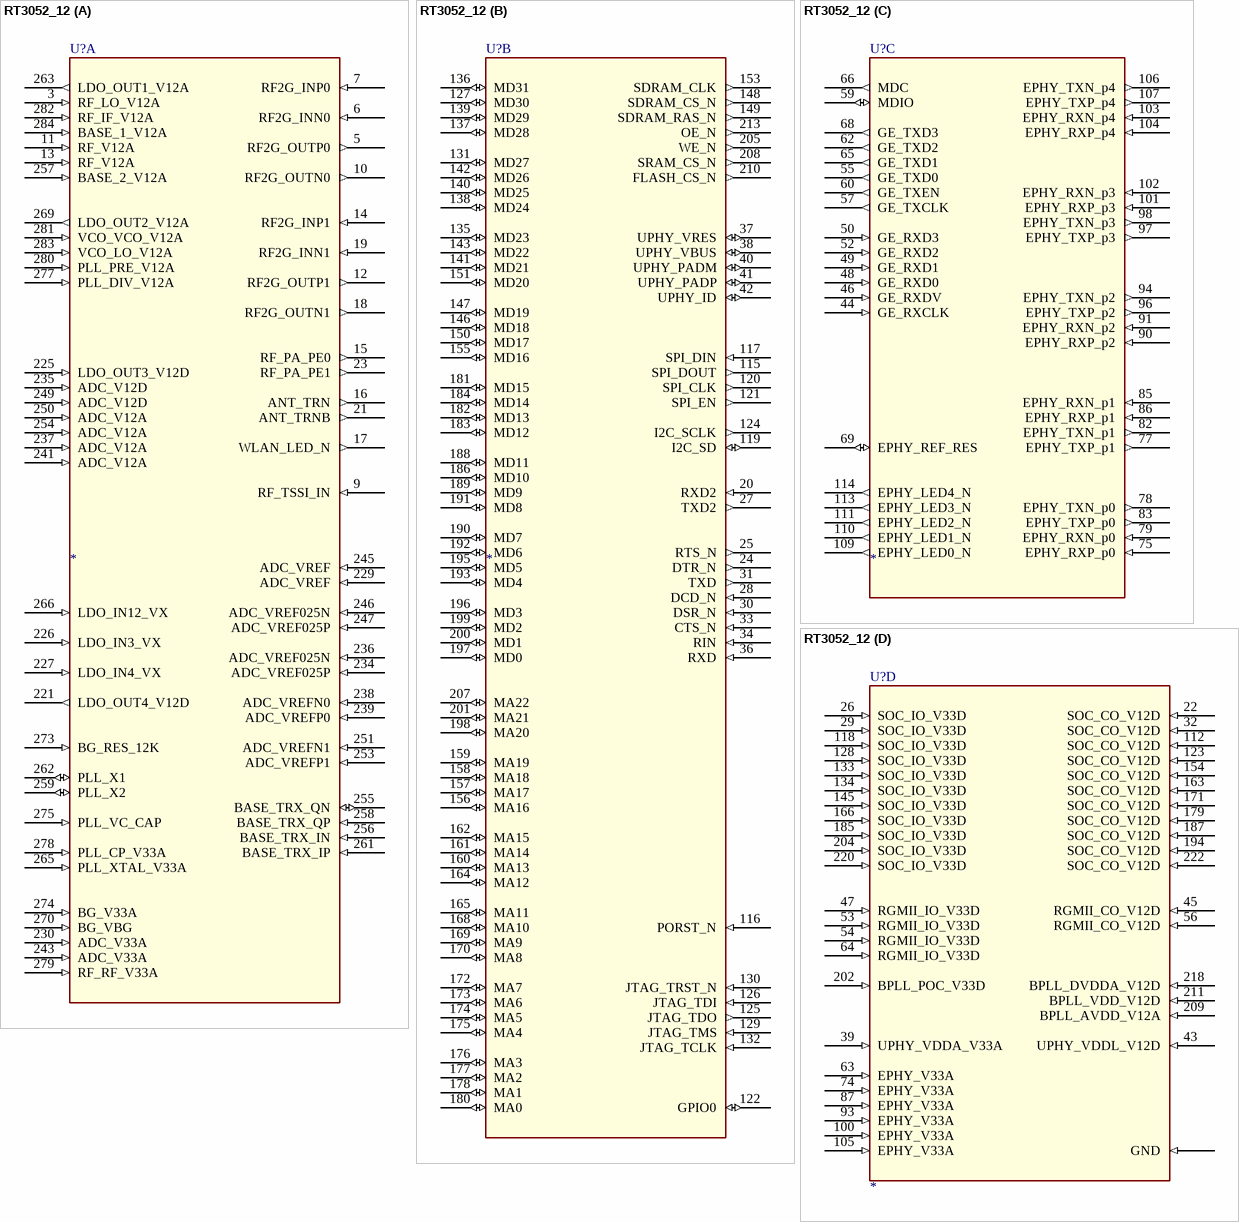
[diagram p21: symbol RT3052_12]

## RT3052_12
designator U?
footprint QFN285
part A pins: 3 RF_LO_V12A (in), 5 RF2G_OUTP0 (out), 6 RF2G_INN0 (in), 7 RF2G_INP0 (in), 9 RF_TSSI_IN (in), 10 RF2G_OUTN0 (out), 11 RF_V12A (in), 12 RF2G_OUTP1 (out), 13 RF_V12A (in), 14 RF2G_INP1 (in), 15 RF_PA_PE0 (out), 16 ANT_TRN (out), 17 WLAN_LED_N (out), 18 RF2G_OUTN1 (out), 19 RF2G_INN1 (in), 21 ANT_TRNB (out), 23 RF_PA_PE1 (out), 221 LDO_OUT4_V12D (out), 225 LDO_OUT3_V12D (in), 226 LDO_IN3_VX (in), 227 LDO_IN4_VX (in), 229 ADC_VREF (in), 230 ADC_V33A (in), 234 ADC_VREF025P (in), 235 ADC_V12D (in), 236 ADC_VREF025N (in), 237 ADC_V12A (in), 238 ADC_VREFN0 (in), 239 ADC_VREFP0 (in), 241 ADC_V12A (in), 243 ADC_V33A (in), 245 ADC_VREF (in), 246 ADC_VREF025N (in), 247 ADC_VREF025P (in), 249 ADC_V12D (in), 250 ADC_V12A (in), 251 ADC_VREFN1 (in), 253 ADC_VREFP1 (in), 254 ADC_V12A (in), 255 BASE_TRX_QN (io), 256 BASE_TRX_IN (in), 257 BASE_2_V12A (in), 258 BASE_TRX_QP (in), 259 PLL_X2 (io), 261 BASE_TRX_IP (in), 262 PLL_X1 (io), 263 LDO_OUT1_V12A (out), 265 PLL_XTAL_V33A (in), 266 LDO_IN12_VX (in), 269 LDO_OUT2_V12A (out), 270 BG_VBG (in), 273 BG_RES_12K (in), 274 BG_V33A (in), 275 PLL_VC_CAP (in), 277 PLL_DIV_V12A (in), 278 PLL_CP_V33A (in), 279 RF_RF_V33A (in), 280 PLL_PRE_V12A (in), 281 VCO_VCO_V12A (in), 282 RF_IF_V12A (in), 283 VCO_LO_V12A (in), 284 BASE_1_V12A (in)
part B pins: 20 RXD2 (in), 24 DTR_N (out), 25 RTS_N (out), 27 TXD2 (out), 28 DCD_N (in), 30 DSR_N (in), 31 TXD (out), 33 CTS_N (in), 34 RIN (in), 36 RXD (in), 37 UPHY_VRES (io), 38 UPHY_VBUS (io), 40 UPHY_PADM (io), 41 UPHY_PADP (io), 42 UPHY_ID (io), 115 SPI_DOUT (out), 116 PORST_N (in), 117 SPI_DIN (in), 119 I2C_SD (io), 120 SPI_CLK (out), 121 SPI_EN (out), 122 GPIO0 (io), 124 I2C_SCLK (out), 125 JTAG_TDO (out), 126 JTAG_TDI (in), 127 MD30 (io), 129 JTAG_TMS (in), 130 JTAG_TRST_N (in), 131 MD27 (io), 132 JTAG_TCLK (in), 135 MD23 (io), 136 MD31 (io), 137 MD28 (io), 138 MD24 (io), 139 MD29 (io), 140 MD25 (io), 141 MD21 (io), 142 MD26 (io), 143 MD22 (io), 146 MD18 (io), 147 MD19 (io), 148 SDRAM_CS_N (out), 149 SDRAM_RAS_N (out), 150 MD17 (io), 151 MD20 (io), 153 SDRAM_CLK (out), 155 MD16 (io), 156 MA16 (io), 157 MA17 (io), 158 MA18 (io), 159 MA19 (io), 160 MA13 (io), 161 MA14 (io), 162 MA15 (io), 164 MA12 (io), 165 MA11 (io), 168 MA10 (io), 169 MA9 (io), 170 MA8 (io), 172 MA7 (io), 173 MA6 (io), 174 MA5 (io), 175 MA4 (io), 176 MA3 (io), 177 MA2 (io), 178 MA1 (io), 180 MA0 (io), 181 MD15 (io), 182 MD13 (io), 183 MD12 (io), 184 MD14 (io), 186 MD10 (io), 188 MD11 (io), 189 MD9 (io), 190 MD7 (io), 191 MD8 (io), 192 MD6 (io), 193 MD4 (io), 195 MD5 (io), 196 MD3 (io), 197 MD0 (io), 198 MA20 (io), 199 MD2 (io), 200 MD1 (io), 201 MA21 (io), 205 WE_N (out), 207 MA22 (io), 208 SRAM_CS_N (out), 210 FLASH_CS_N (out), 213 OE_N (out)
part C pins: 44 GE_RXCLK (in), 46 GE_RXDV (in), 48 GE_RXD0 (in), 49 GE_RXD1 (in), 50 GE_RXD3 (in), 52 GE_RXD2 (in), 55 GE_TXD0 (out), 57 GE_TXCLK (out), 59 MDIO (io), 60 GE_TXEN (out), 62 GE_TXD2 (out), 65 GE_TXD1 (out), 66 MDC (out), 68 GE_TXD3 (out), 69 EPHY_REF_RES (io), 75 EPHY_RXP_p0 (in), 77 EPHY_TXP_p1 (out), 78 EPHY_TXN_p0 (out), 79 EPHY_RXN_p0 (in), 82 EPHY_TXN_p1 (out), 83 EPHY_TXP_p0 (out), 85 EPHY_RXN_p1 (in), 86 EPHY_RXP_p1 (in), 90 EPHY_RXP_p2 (in), 91 EPHY_RXN_p2 (in), 94 EPHY_TXN_p2 (out), 96 EPHY_TXP_p2 (out), 97 EPHY_TXP_p3 (out), 98 EPHY_TXN_p3 (out), 101 EPHY_RXP_p3 (in), 102 EPHY_RXN_p3 (in), 103 EPHY_RXN_p4 (in), 104 EPHY_RXP_p4 (in), 106 EPHY_TXN_p4 (out), 107 EPHY_TXP_p4 (out), 109 EPHY_LED0_N (out), 110 EPHY_LED1_N (out), 111 EPHY_LED2_N (out), 113 EPHY_LED3_N (out), 114 EPHY_LED4_N (out)
part D pins: 22 SOC_CO_V12D (in), 26 SOC_IO_V33D (in), 29 SOC_IO_V33D (in), 32 SOC_CO_V12D (in), 39 UPHY_VDDA_V33A (in), 43 UPHY_VDDL_V12D (in), 45 RGMII_CO_V12D (in), 47 RGMII_IO_V33D (in), 53 RGMII_IO_V33D (in), 54 RGMII_IO_V33D (in), 56 RGMII_CO_V12D (in), 63 EPHY_V33A (in), 64 RGMII_IO_V33D (in), 74 EPHY_V33A (in), 87 EPHY_V33A (in), 93 EPHY_V33A (in), 100 EPHY_V33A (in), 105 EPHY_V33A (in), 112 SOC_CO_V12D (in), 118 SOC_IO_V33D (in), 123 SOC_CO_V12D (in), 128 SOC_IO_V33D (in), 133 SOC_IO_V33D (in), 134 SOC_IO_V33D (in), 145 SOC_IO_V33D (in), 154 SOC_CO_V12D (in), 163 SOC_CO_V12D (in), 166 SOC_IO_V33D (in), 171 SOC_CO_V12D (in), 179 SOC_CO_V12D (in), 185 SOC_IO_V33D (in), 187 SOC_CO_V12D (in), 194 SOC_CO_V12D (in), 202 BPLL_POC_V33D (in), 204 SOC_IO_V33D (in), 209 BPLL_AVDD_V12A (in), 211 BPLL_VDD_V12D (in), 218 BPLL_DVDDA_V12D (in), 220 SOC_IO_V33D (in), 222 SOC_CO_V12D (in), GND (in)

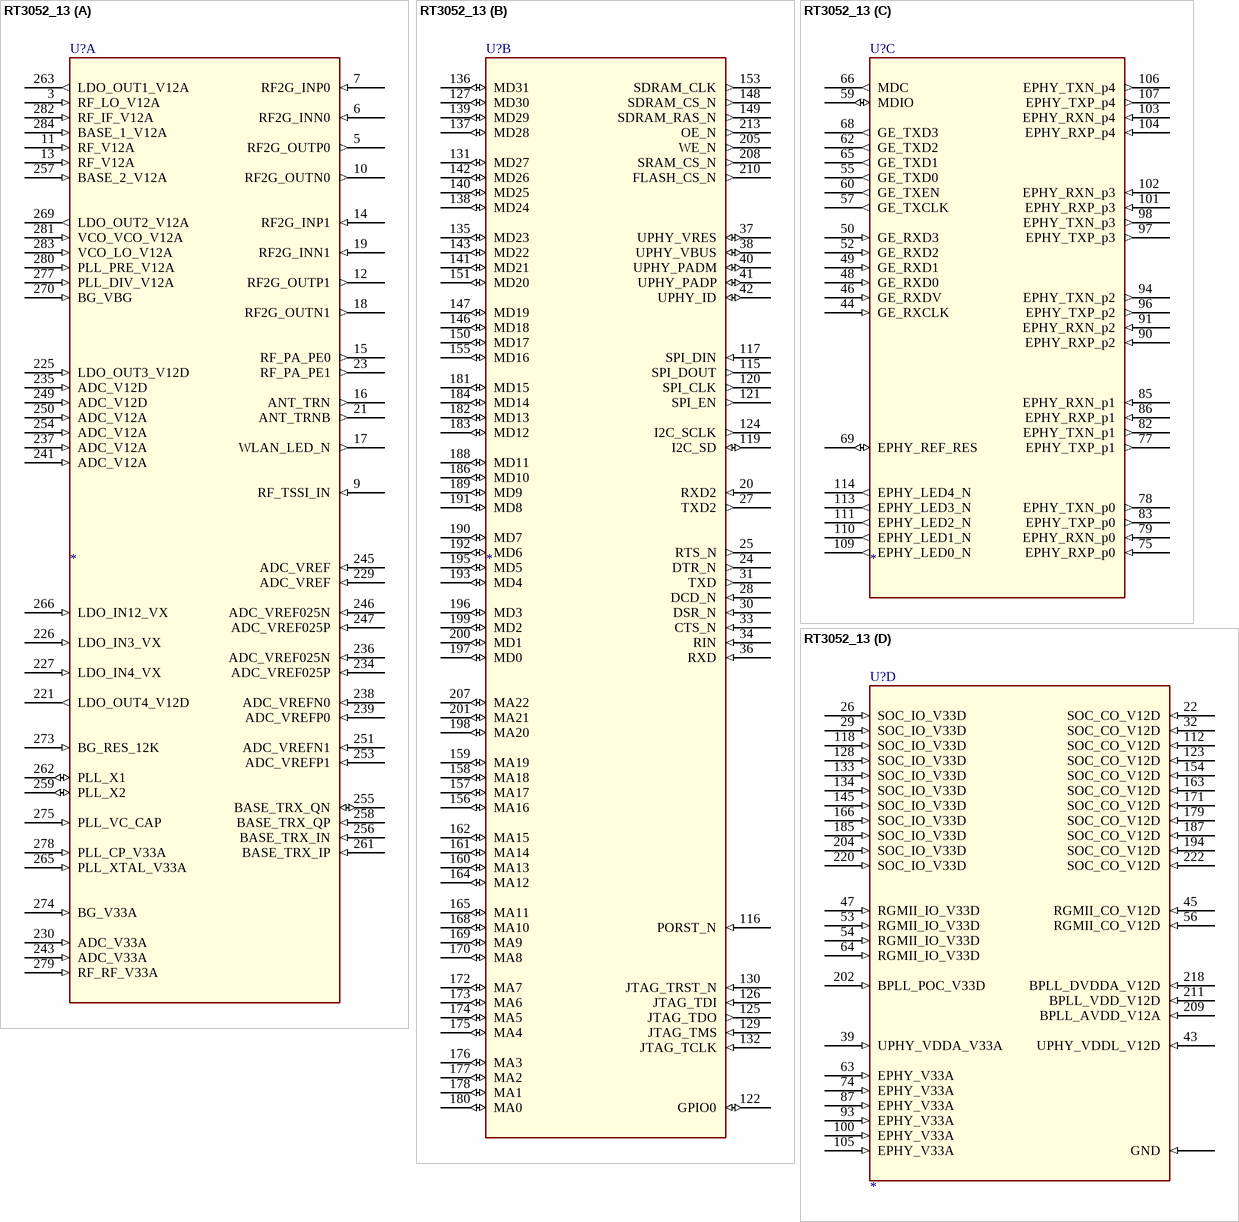
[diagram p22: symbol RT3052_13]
